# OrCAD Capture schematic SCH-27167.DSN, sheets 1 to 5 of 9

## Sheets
1 TWR-K60F120M MCU: size C; title: TWR-K60F120M; rev: B; company: Freescale Semiconductor; note: SCH-27167 PDF: SPF-27167; note: 6501 William Cannon Drive West; note: Austin, TX 78735-8598
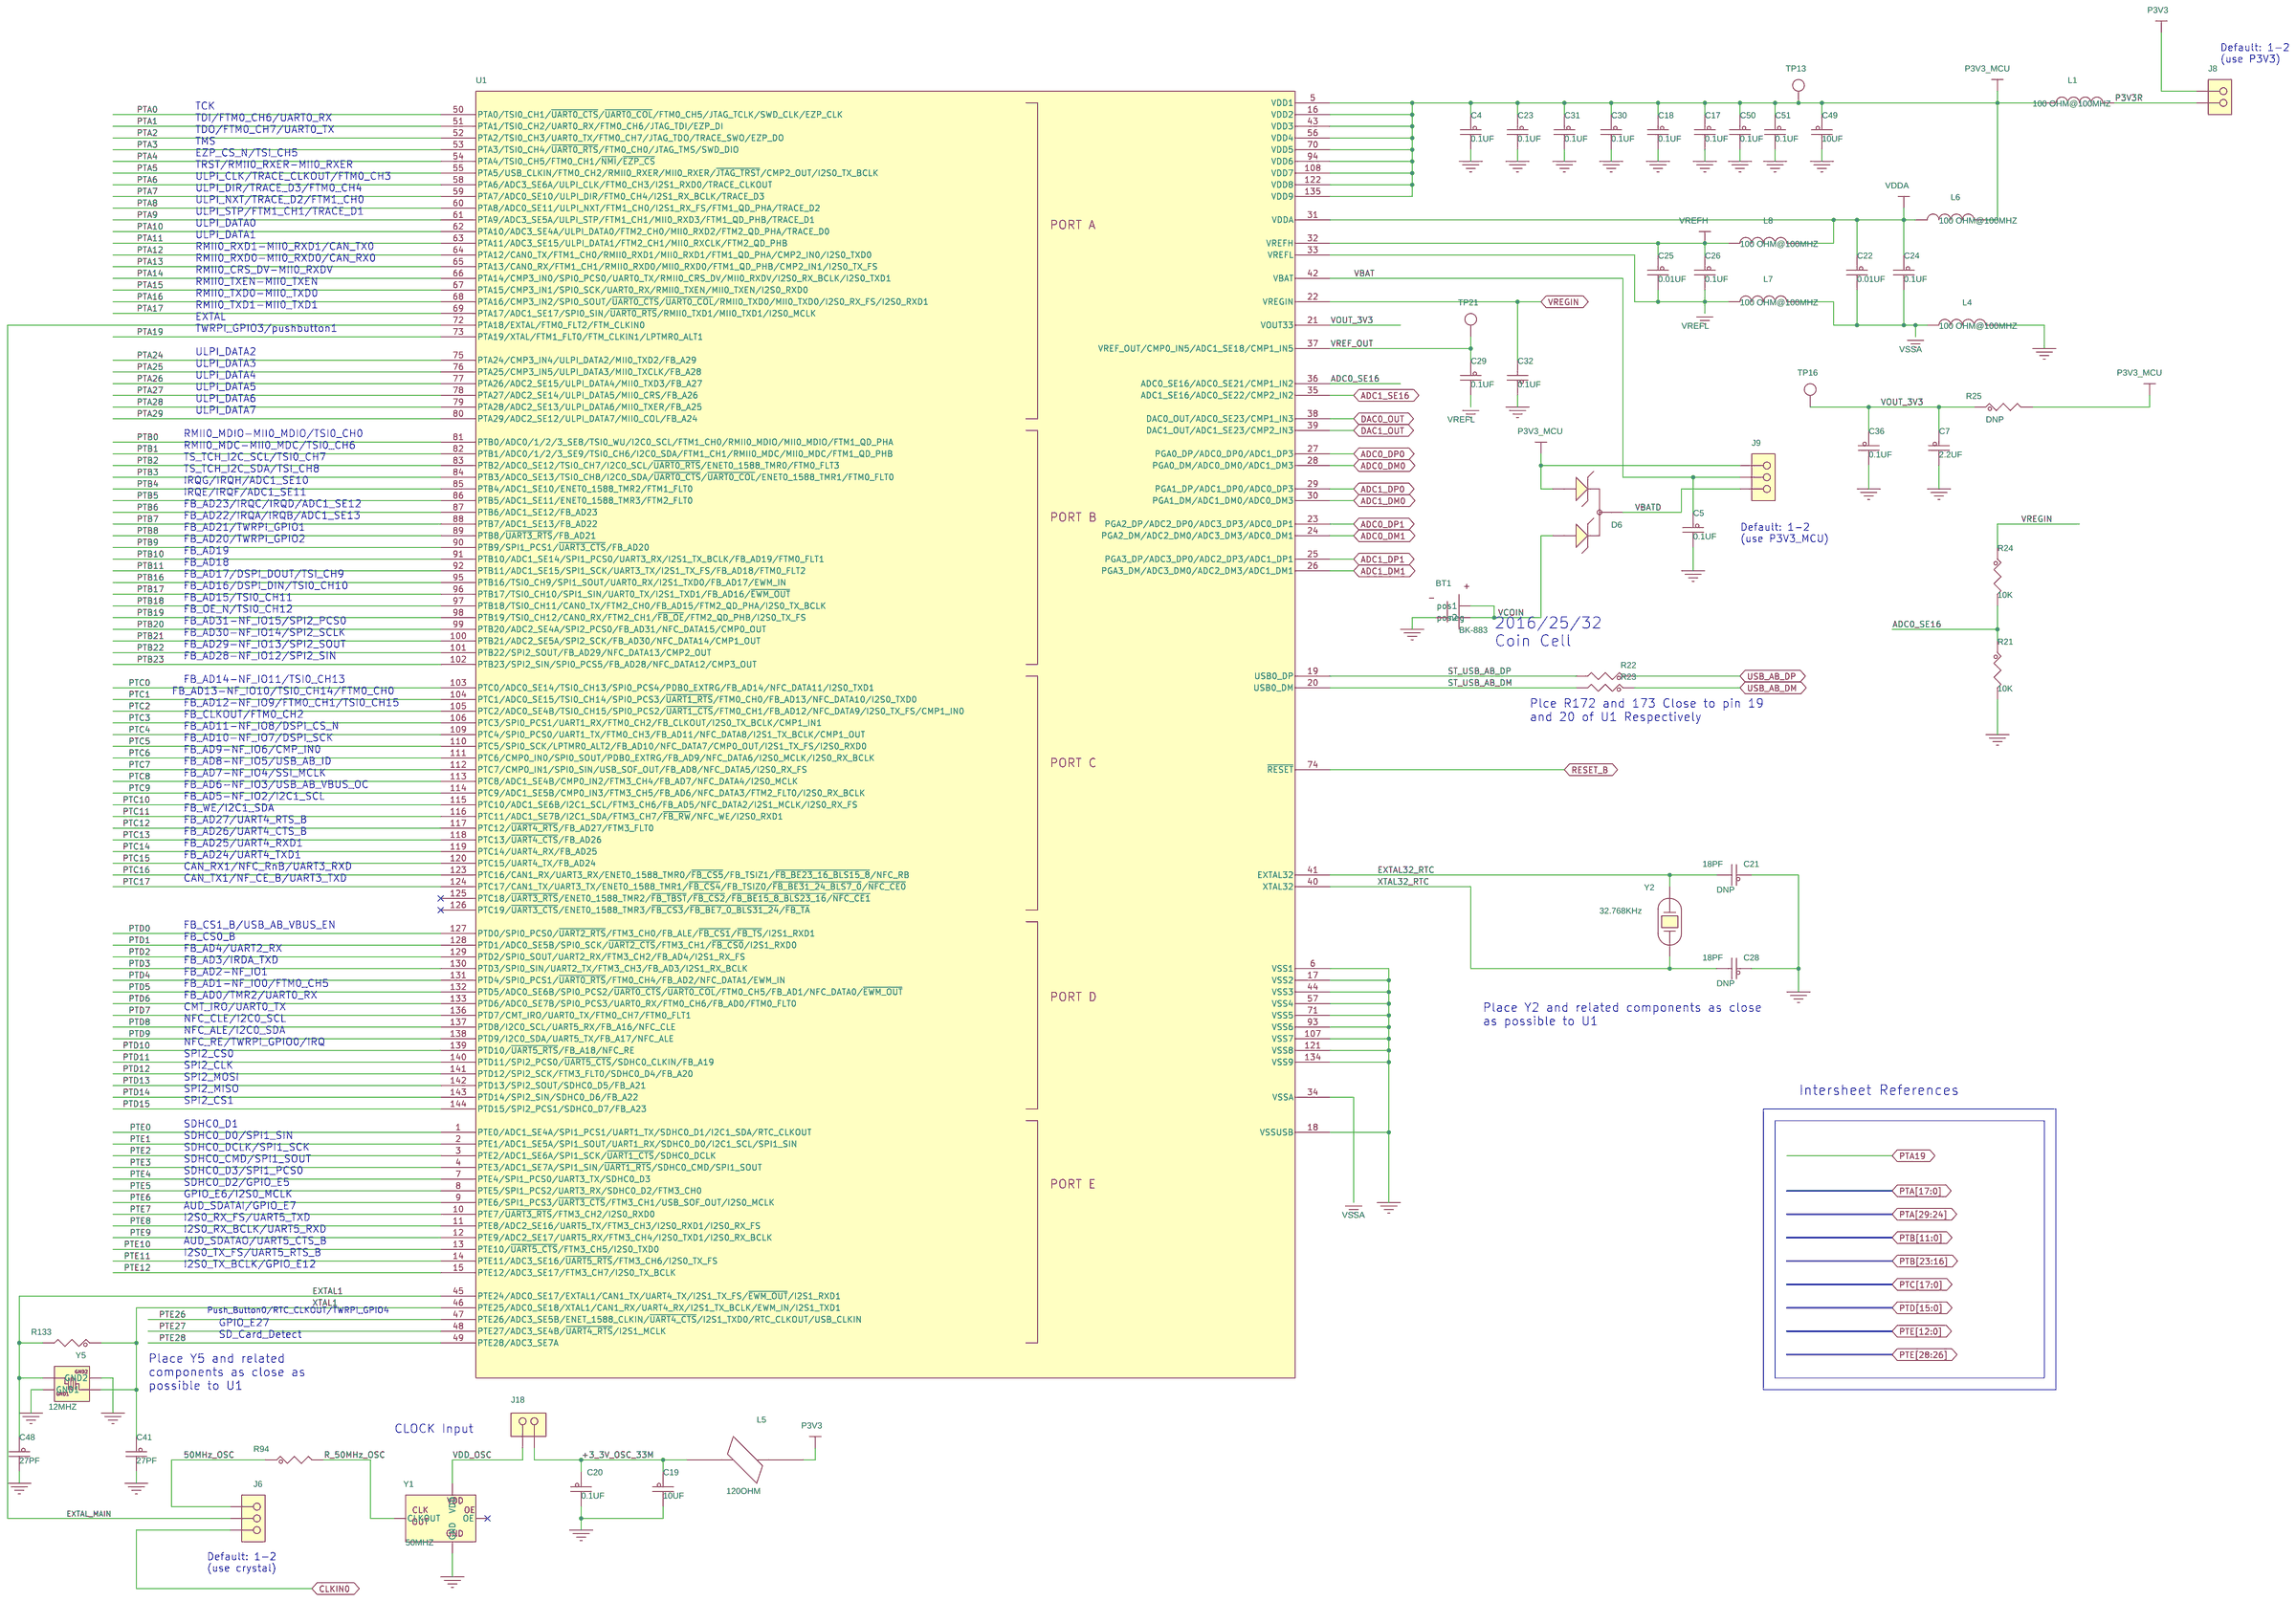
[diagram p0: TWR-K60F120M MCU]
2 USB/OSBDM/VTRAN/PWR: size C
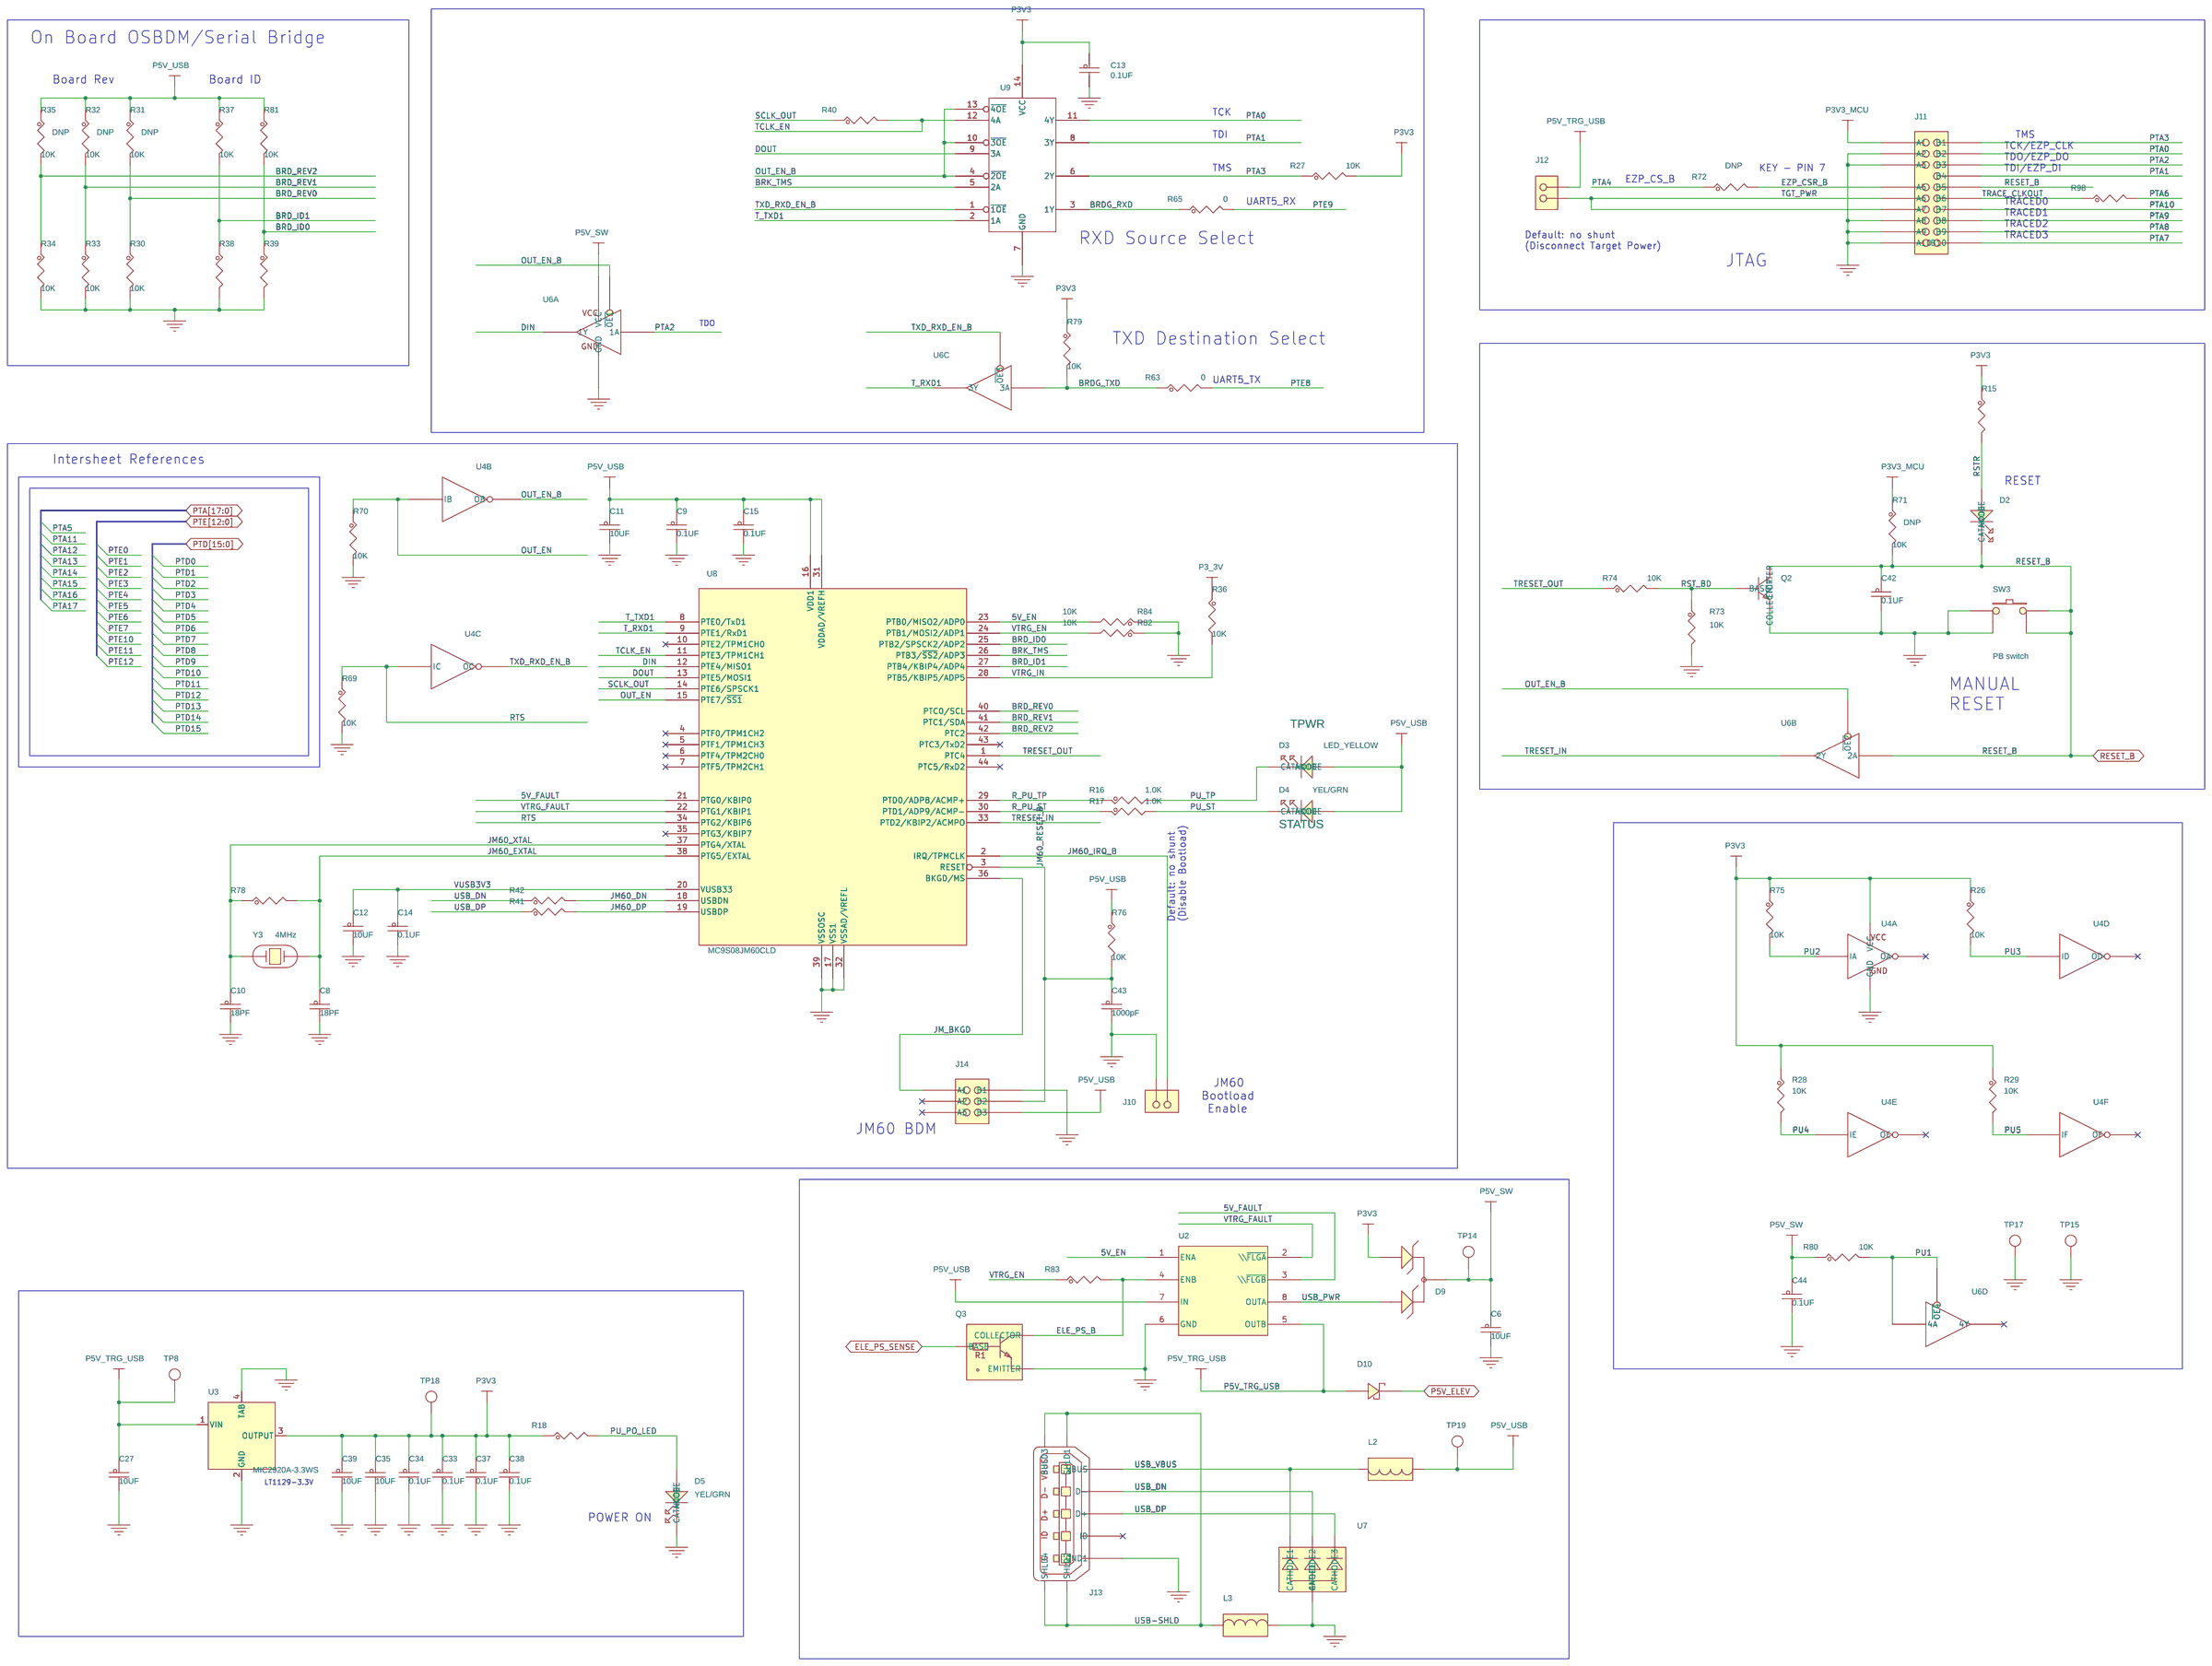
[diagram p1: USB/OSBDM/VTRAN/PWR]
3 Peripherals: size C
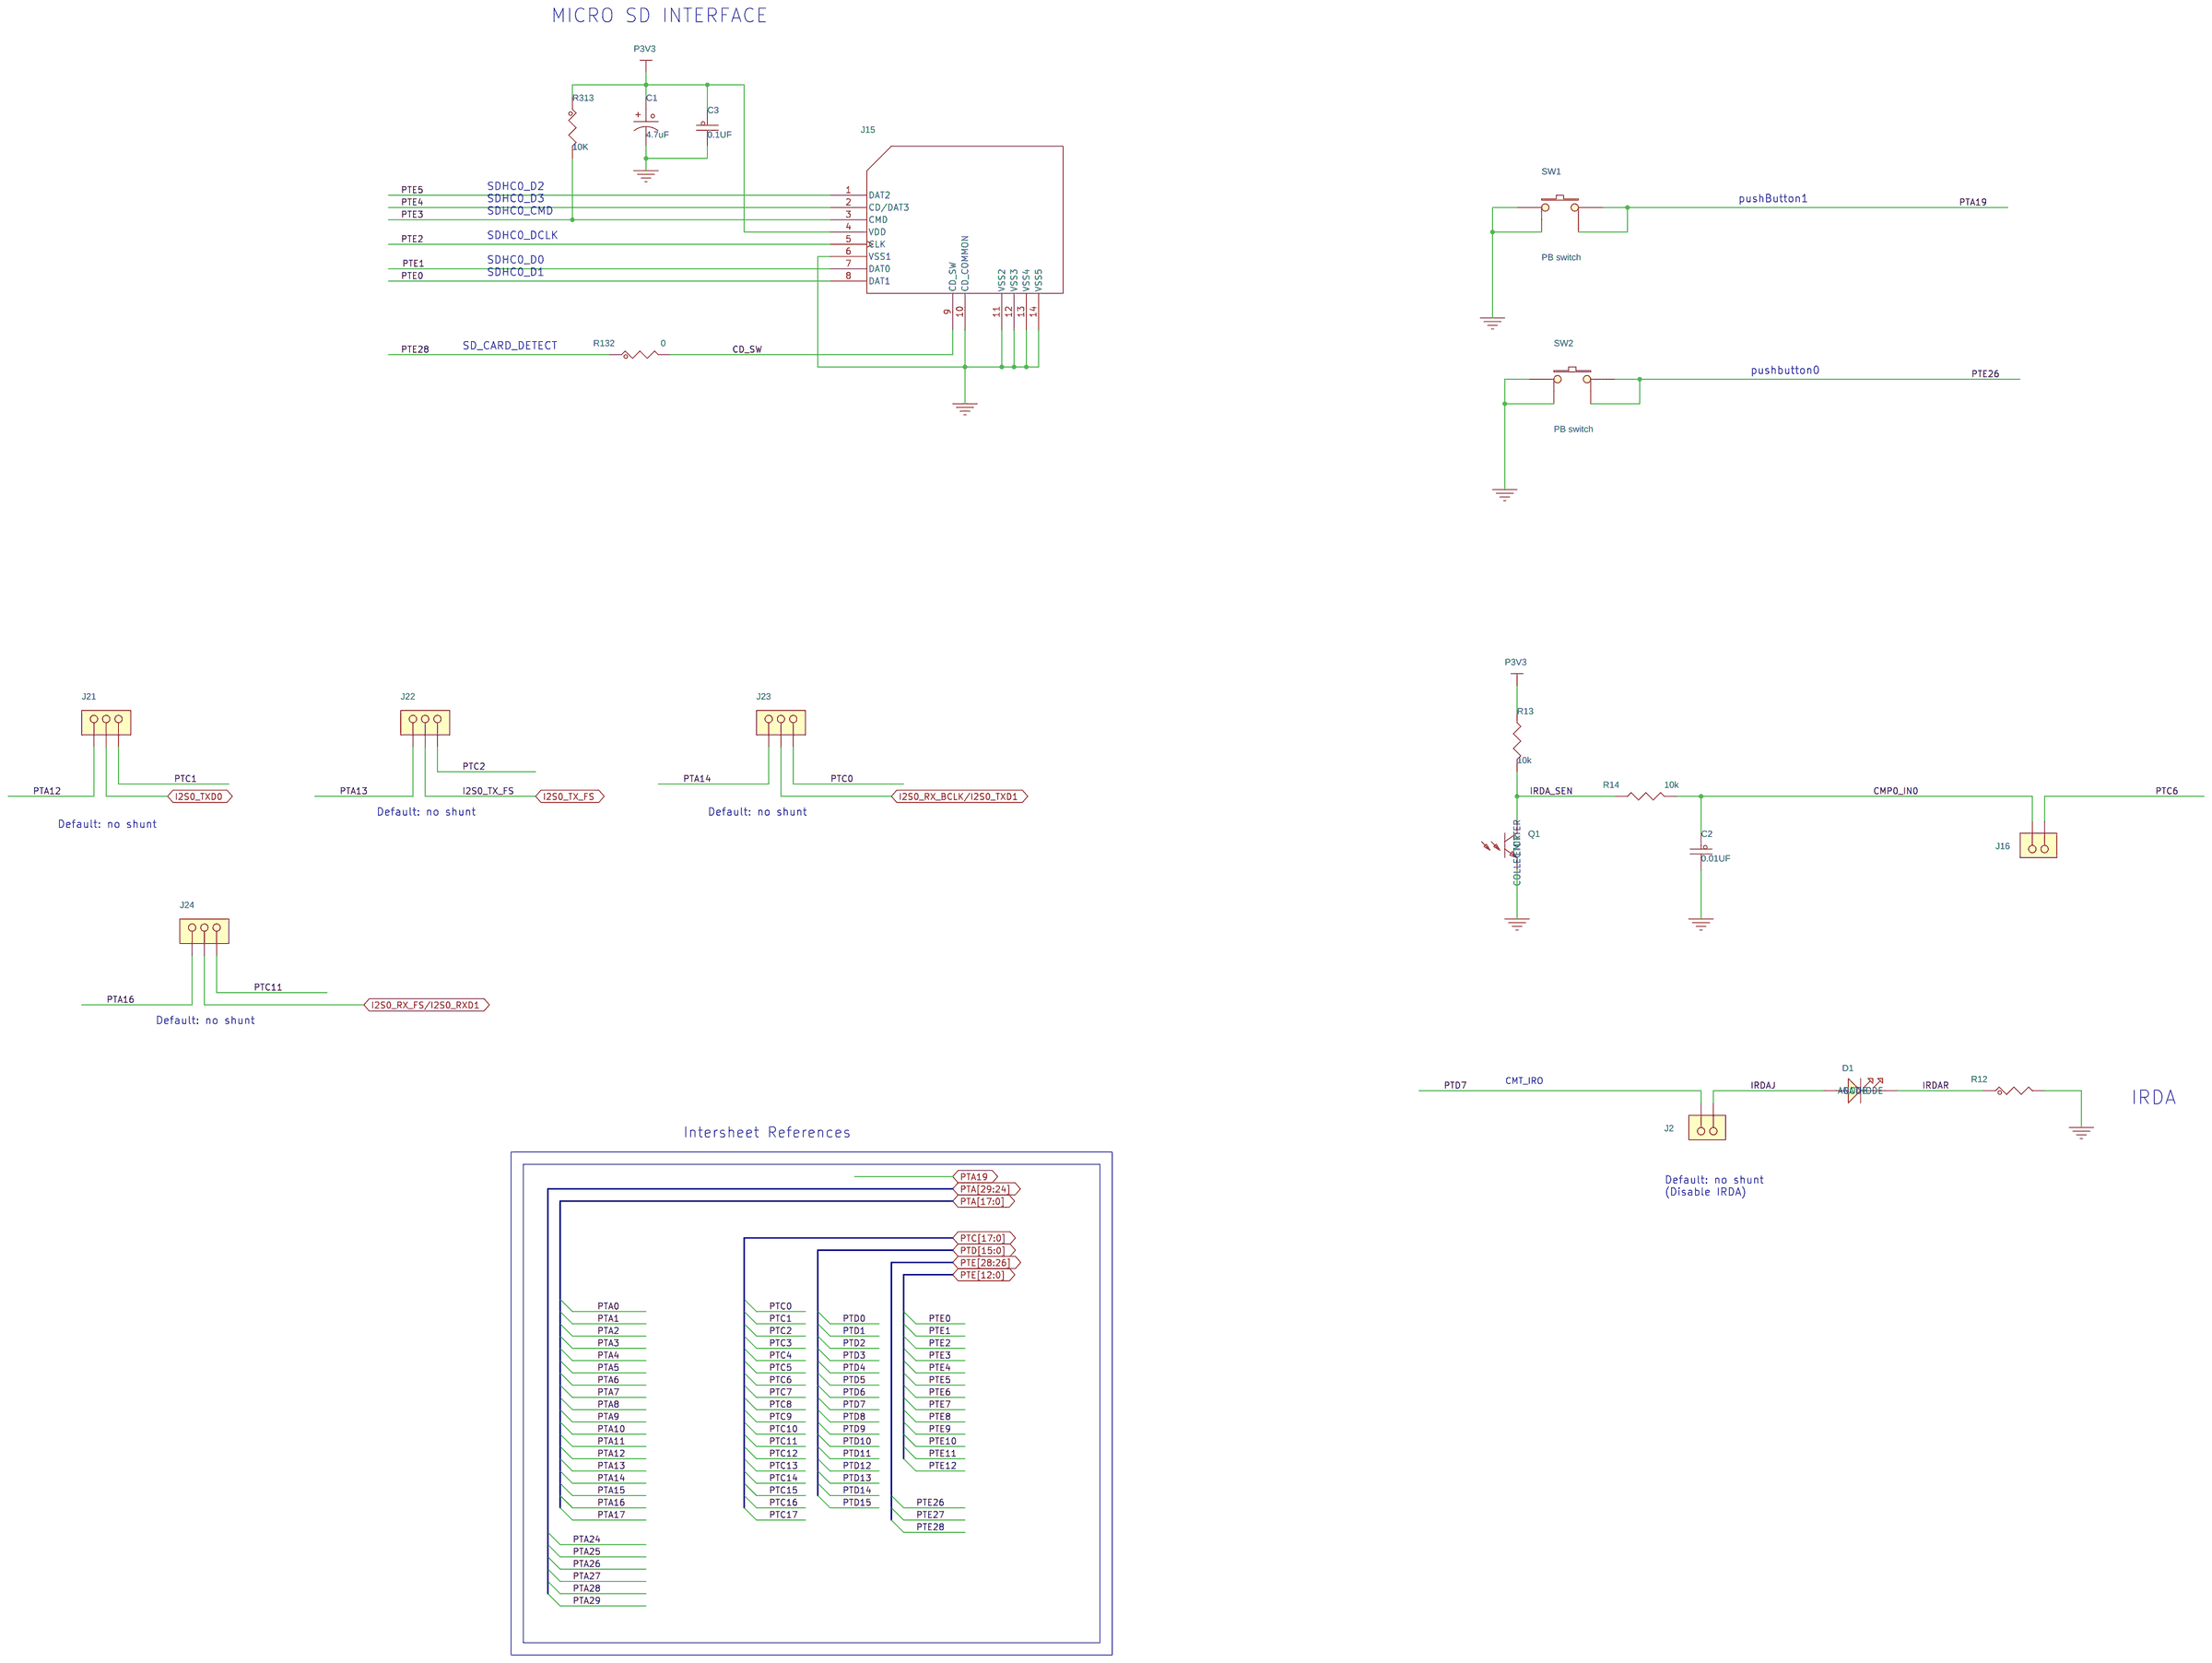
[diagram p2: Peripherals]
4 Sensors: size C
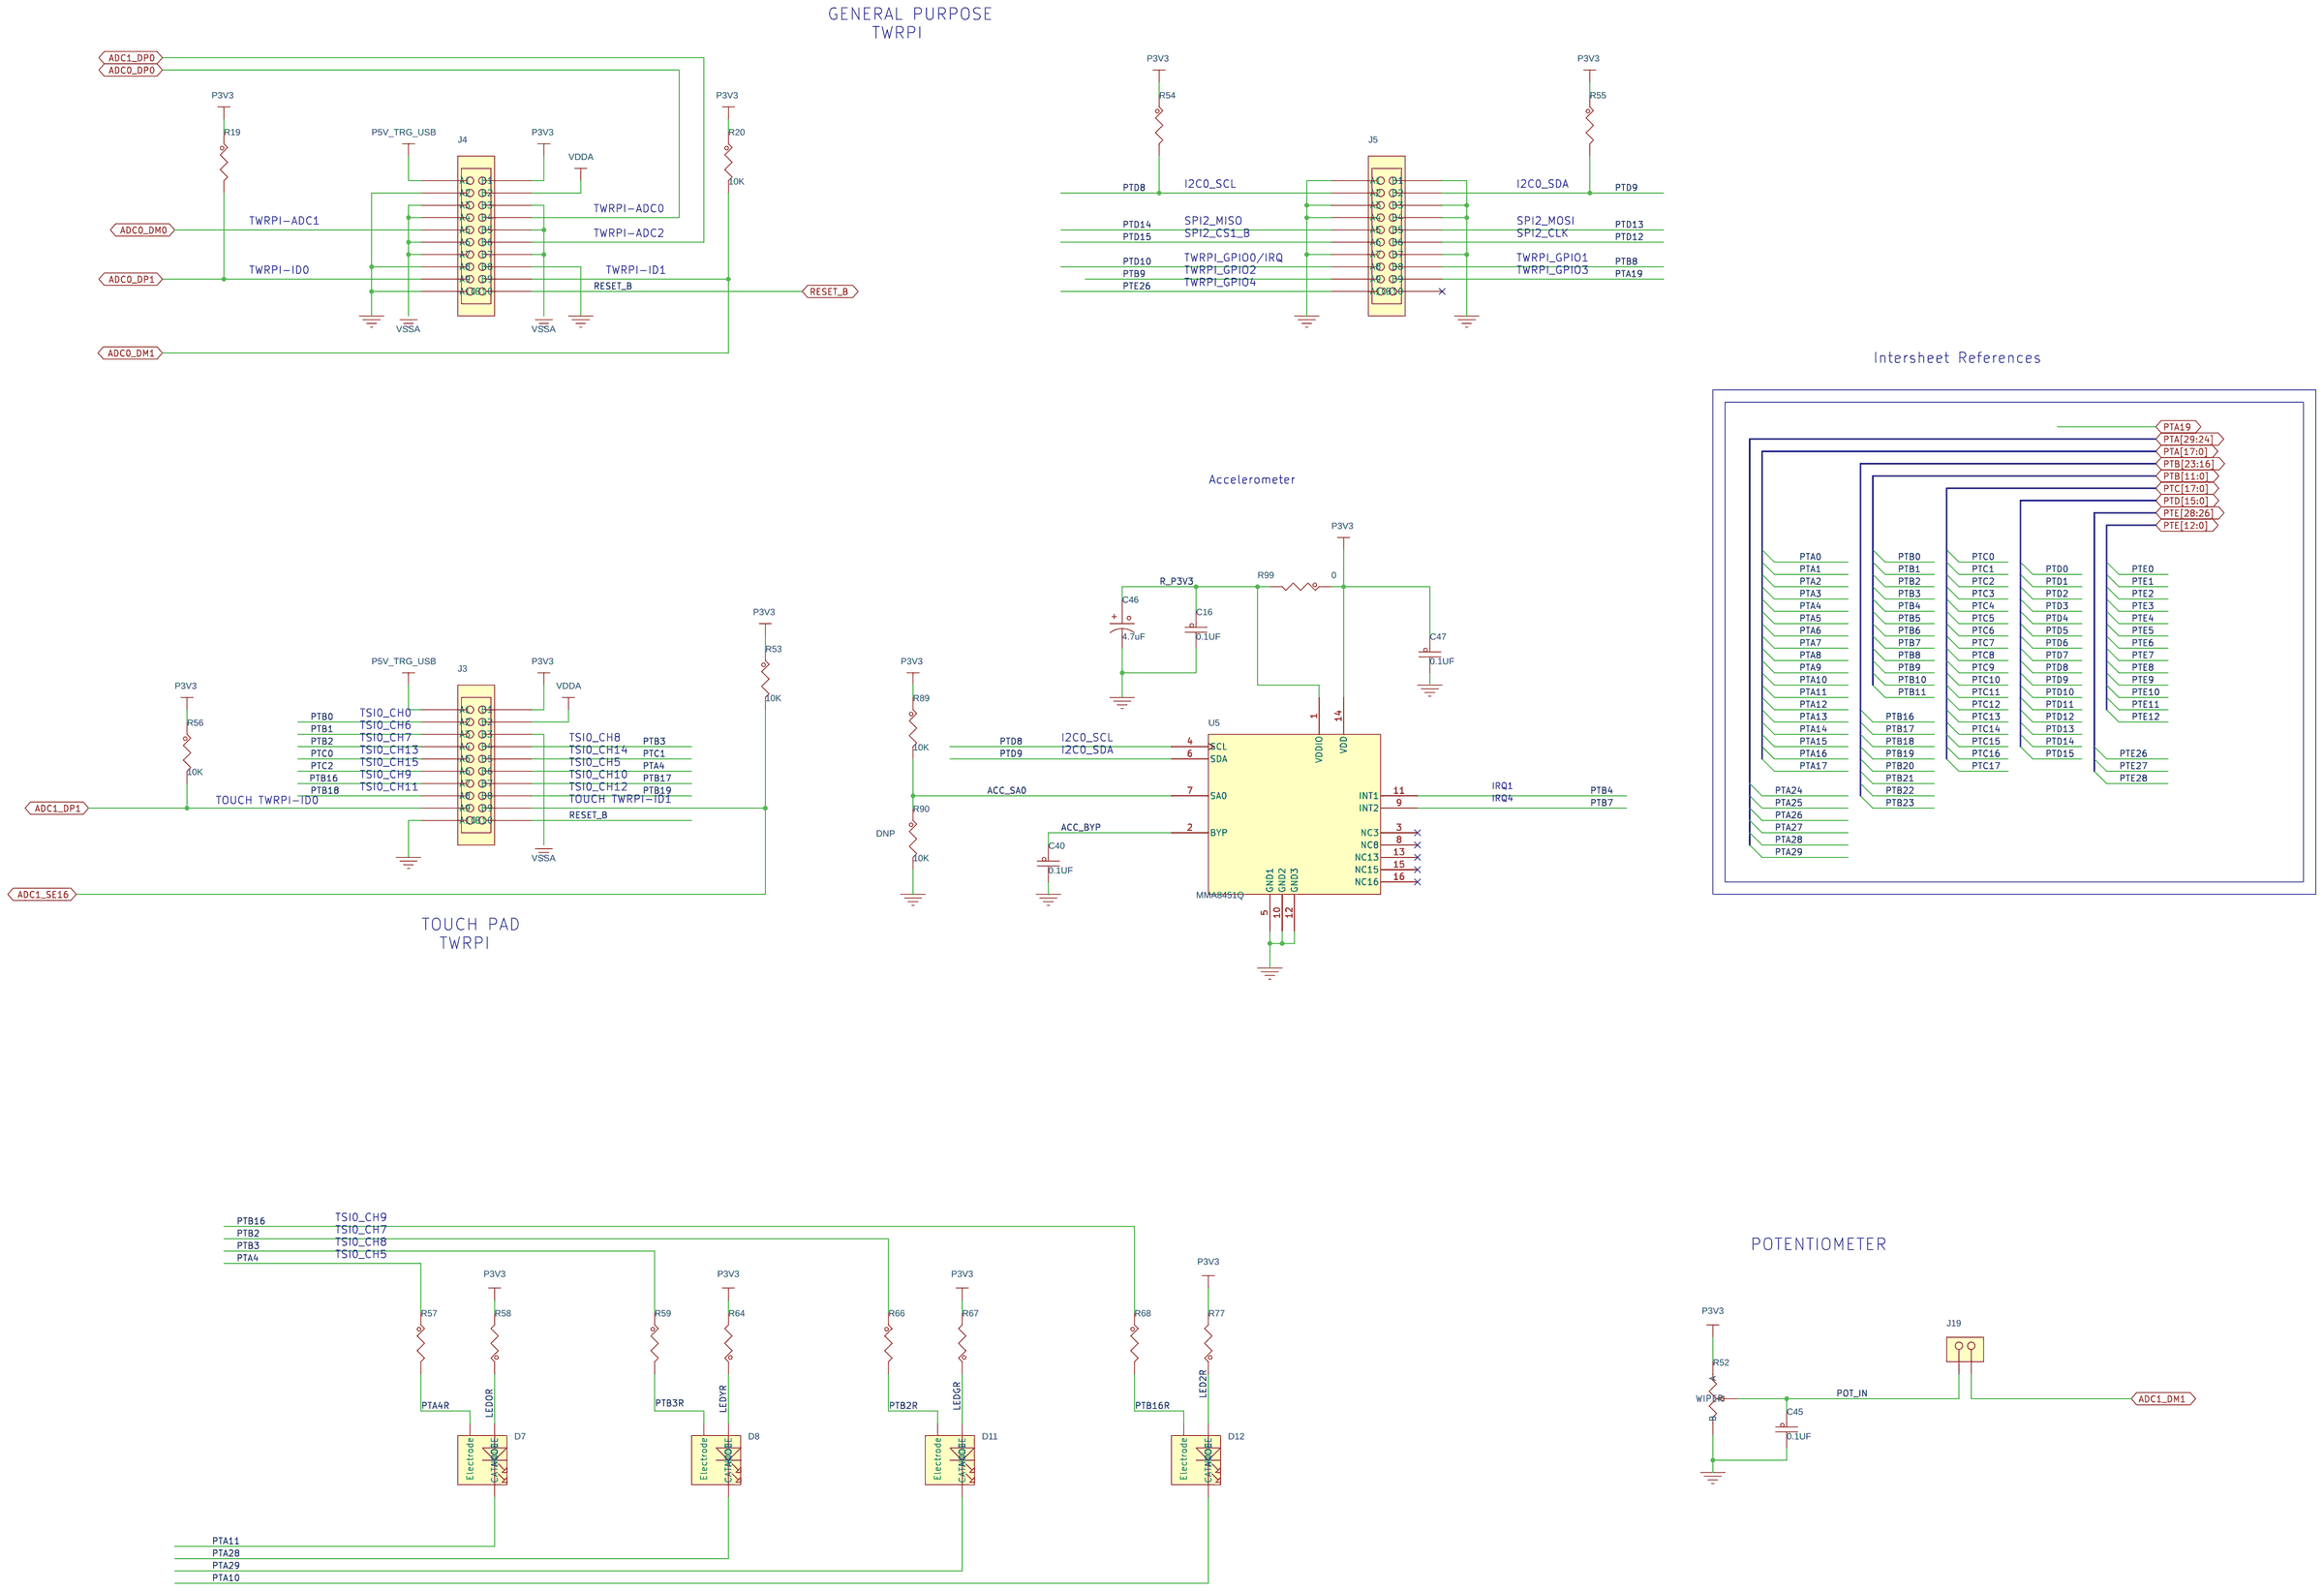
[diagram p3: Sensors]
5 NAND_Flash: size C
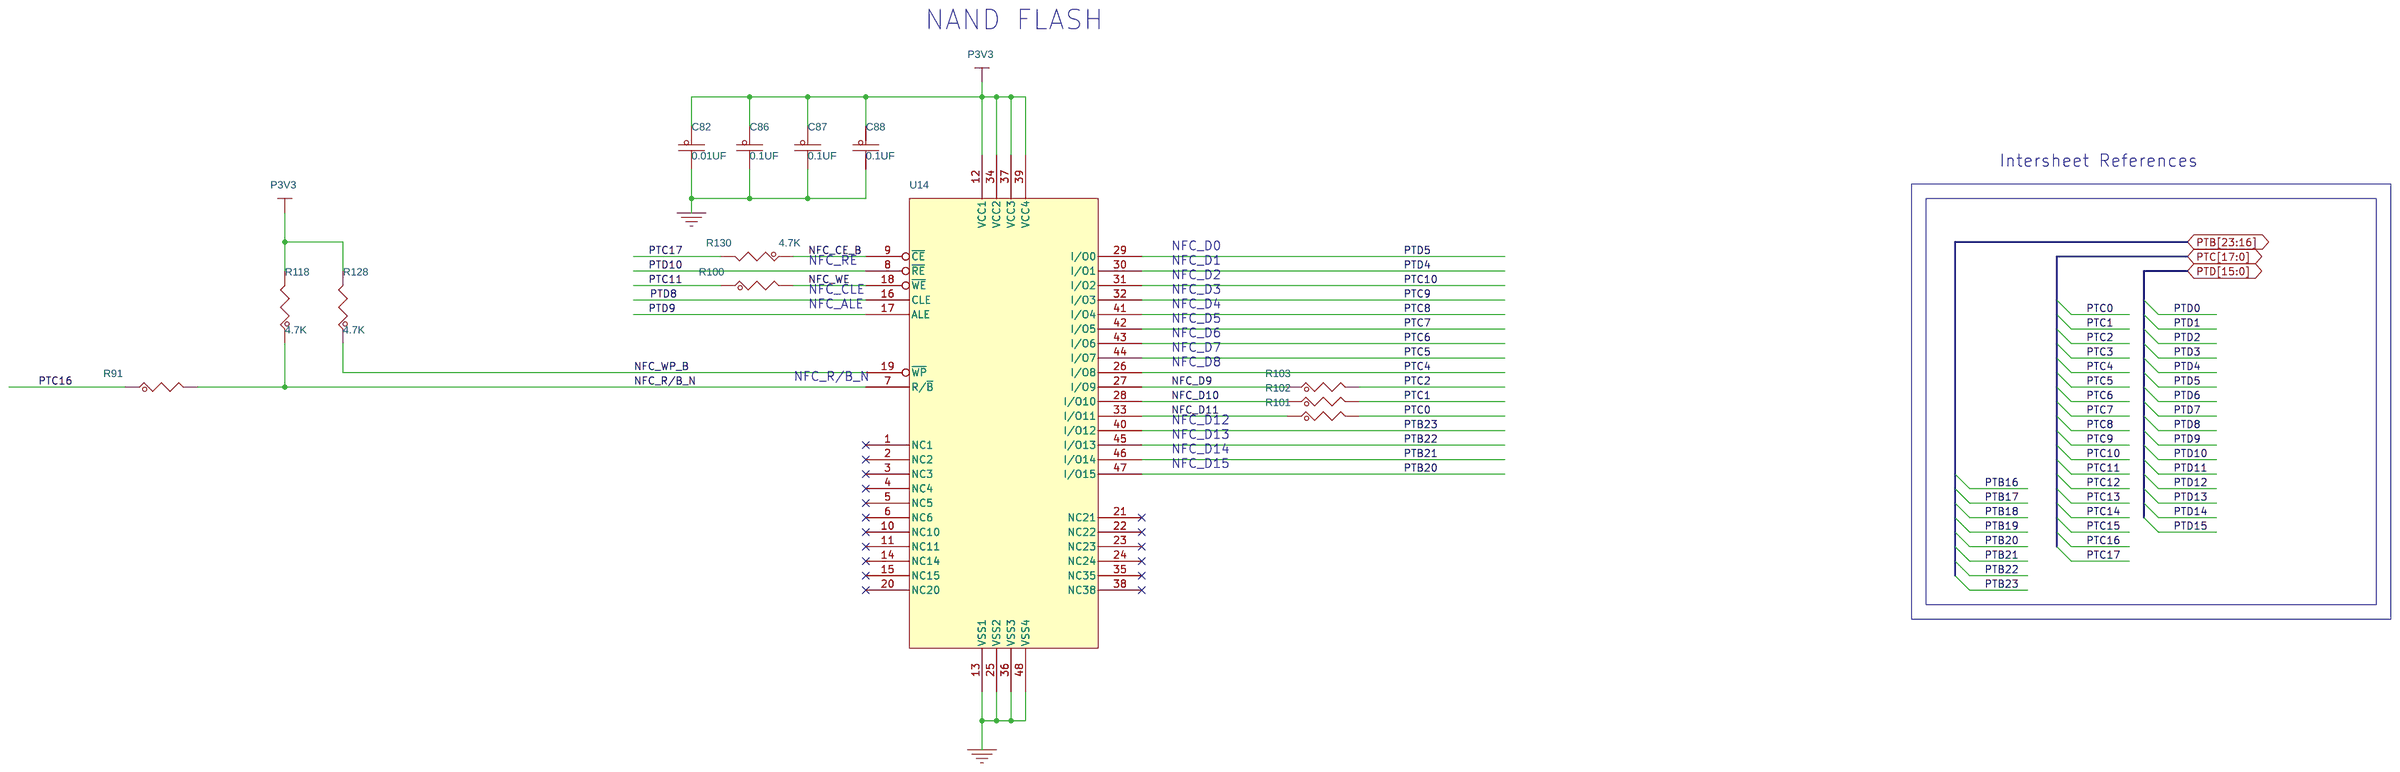
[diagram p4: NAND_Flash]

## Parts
sheet NAND_Flash
C82  0.01UF  [CC0402_25]
C86  0.1UF  [CC0603_OV]
C87  0.1UF  [CC0603_OV]
C88  0.1UF  [CC0603_OV]
R91  0  [RC0603_OV]
R100  0  [RC0603_OV]
R101  0  [RC0603_OV]
R102  0  [RC0603_OV]
R103  0  [RC0603_OV]
R118  4.7K  [RC0402_25]
R128  4.7K  [RC0402_25]
R130  4.7K  [RC0402_25]
U14  MT29F2G16ABAEAWP:E  [tsop48_18p5x12p4]
sheet Peripherals
C1  4.7uF  [cc3528-21]
C2  0.01UF  [CC0402_25]
C3  0.1UF  [CC0603_OV]
D1  QTLP610CIR  [diode_3p2x2p2]
J2  HDR 1X2 TH  [HDR102]
J15  Conn MicroSD  [CON_SDCARD_8F_SM_RA]
J16  HDR 1X2 TH  [HDR102]
J21  HDR TH 1X3  [HDR103]
J22  HDR TH 1X3  [HDR103]
J23  HDR TH 1X3  [HDR103]
J24  HDR TH 1X3  [HDR103]
Q1  QTLP610CPD  [QTLP610]
R12  33  [RC0603_OV]
R13  10k  [RC0402_25]
R14  10k  [RC0402_25]
R132  0  [RC0603_OV]
R313  10K  [RC0603_OV]
SW1  PB switch  [SW4_4MM]
SW2  PB switch  [SW4_4MM]
sheet Sensors
C16  0.1UF  [CC0603_OV]
C40  0.1UF  [CC0603_OV]
C45  0.1UF  [CC0603_OV]
C46  4.7uF  [cc3528-21]
C47  0.1UF  [CC0603_OV]
D7  LED_OR + ELECTRODE  [led2_electrode]
D8  LED_YEL + ELECTRODE  [LED2_ELECTRODE]
D11  LED_GRN + ELECTRODE  [LED2_ELECTRODE]
D12  LED2_ELECTRODE  [LED2_ELECTRODE]
J3  CON_2X10  [con_tfm_20m_50_sm]
J4  CON_2X10  [con_tfm_20m_50_sm]
J5  CON_2X10  [con_tfm_20m_50_sm]
J19  HDR 1X2 TH  [HDR102]
R19  10K  [RC0603_OV]
R20  10K  [RC0603_OV]
R52  5K  [pot3_3352t]
R53  10K  [RC0603_OV]
R54  4.70K  [RC0603_OV]
R55  4.70K  [RC0603_OV]
R56  10K  [RC0603_OV]
R57  0  [RC0603_OV]
R58  1.0K  [RC0402_25]
R59  0  [RC0603_OV]
R64  1.0K  [RC0402_25]
R66  0  [RC0603_OV]
R67  1.0K  [RC0402_25]
R68  0  [RC0603_OV]
R77  1.0K  [RC0402_25]
R89  10K  [RC0603_OV]
R90  10K  [RC0603_OV]
R99  0  [RC0603_OV]
U5  MMA8451Q  [QFN5X3_0P5_3X3]
sheet TWR-K60F120M MCU
BT1  BK-883  [skt_bat_780x1210]
C4  0.1UF  [CC0603_OV]
C5  0.1UF  [CC0603_OV]
C7  2.2UF  [CC0603_OV]
C17  0.1UF  [CC0603_OV]
C18  0.1UF  [CC0603_OV]
C19  10UF  [CC0805_OV]
C20  0.1UF  [CC0603_OV]
C21  18PF  [CC0603_OV]
C22  0.01UF  [CC0402_25]
C23  0.1UF  [CC0603_OV]
C24  0.1UF  [CC0603_OV]
C25  0.01UF  [CC0402_25]
C26  0.1UF  [CC0603_OV]
C28  18PF  [CC0603_OV]
C29  0.1UF  [CC0603_OV]
C30  0.1UF  [CC0603_OV]
C31  0.1UF  [CC0603_OV]
C32  0.1UF  [CC0603_OV]
C36  0.1UF  [CC0603_OV]
C41  27PF  [CC0402_25]
C48  27PF  [CC0402_25]
C49  10UF  [CC0805_OV]
C50  0.1UF  [CC0603_OV]
C51  0.1UF  [CC0603_OV]
D6  BAT54C  [sot-23]
J6  HDR TH 1X3  [HDR103]
J8  HDR 1X2 TH  [HDR102]
J9  HDR TH 1X3  [HDR103]
J18  HDR 1X2 TH  [HDR102]
L1  100 OHM@100MHZ  [IND_0603]
L4  100 OHM@100MHZ  [IND_0603]
L5  120OHM  [IND_0603]
L6  100 OHM@100MHZ  [IND_0603]
L7  100 OHM@100MHZ  [IND_0603]
L8  100 OHM@100MHZ  [IND_0603]
R21  10K  [RC0603_OV]
R22  33  [RC0603_OV]
R23  33  [RC0603_OV]
R24  10K  [RC0603_OV]
R25  0  [RC0805_OV]
R94  68  [RC0402_25]
R133  10M  [RC0402_25]
TP13  TPAD_040  [TPAD_040]
TP16  TPAD_040  [TPAD_040]
TP21  TPAD_040  [TPAD_040]
U1  PK60FN1M0VLQ12  [LQFP144_0P5_20X20MM]
Y1  50MHZ  [XTLOSC4_SM]
Y2  32.768KHz  [XTL2_ECS_SM]
Y5  12MHZ  [xtal4_3p3x2p6_sm_fl]
sheet USB/OSBDM/VTRAN/PWR
C6  10UF  [CC0805_OV]
C8  18PF  [CC0603_OV]
C9  0.1UF  [CC0603_OV]
C10  18PF  [CC0603_OV]
C11  10UF  [CC0805_OV]
C12  10UF  [CC0805_OV]
C13  0.1UF  [CC0603_OV]
C14  0.1UF  [CC0603_OV]
C15  0.1UF  [CC0603_OV]
C27  10UF  [CC0805_OV]
C33  0.1UF  [CC0603_OV]
C34  0.1UF  [CC0603_OV]
C35  10UF  [CC0805_OV]
C37  0.1UF  [CC0603_OV]
C38  0.1UF  [CC0603_OV]
C39  10UF  [CC0805_OV]
C42  0.1UF  [CC0603_OV]
C43  1000pF  [CC0805_OV]
C44  0.1UF  [CC0603_OV]
D2  ORANGE  [LED_0603]
D3  LED_YELLOW  [LED_0603]
D4  YEL/GRN  [LED_0603]
D5  YEL/GRN  [LED_0603]
D9  BAT54C  [sot-23]
D10  MSS1P3L  [smb_2p7x1p4]
J10  HDR 1X2 TH  [HDR102]
J11  HDR_19P  [con_ftsh_19m_50_sm]
J12  HDR 1X2 TH  [HDR102]
J13  CONN USB MINI-B 1x5  [con5_usb_mini_a_smt]
J14  HDR_2X3  [HDR203_TSM_SM]
L2  330 OHM  [IND_0805]
L3  330 OHM  [IND_0805]
Q2  MMBT3904LT1G  [SOT23]
Q3  PDTC115T  [sot416]
R15  330  [RC0402_25]
R16  1.0K  [RC0402_25]
R17  1.0K  [RC0402_25]
R18  270  [RC0402_25]
R26  10K  [RC0603_OV]
R27  10K  [RC0603_OV]
R28  10K  [RC0603_OV]
R29  10K  [RC0603_OV]
R30  10K  [RC0603_OV]
R31  10K  [RC0603_OV]
R32  10K  [RC0603_OV]
R33  10K  [RC0603_OV]
R34  10K  [RC0603_OV]
R35  10K  [RC0603_OV]
R36  10K  [RC0603_OV]
R37  10K  [RC0603_OV]
R38  1.3K  [RC0402_25]
R39  1.3K  [RC0402_25]
R40  4.99K  [RC0402_25]
R41  33  [RC0603_OV]
R42  33  [RC0603_OV]
R63  0  [RC0603_OV]
R65  0  [RC0603_OV]
R69  10K  [RC0603_OV]
R70  10K  [RC0603_OV]
R71  10K  [RC0603_OV]
R72  0  [RC0603_OV]
R73  10K  [RC0603_OV]
R74  10K  [RC0603_OV]
R75  10K  [RC0603_OV]
R76  10K  [RC0603_OV]
R78  10M  [RC0402_25]
R79  10K  [RC0603_OV]
R80  10K  [RC0603_OV]
R81  10K  [RC0603_OV]
R82  10K  [RC0603_OV]
R83  2.2K  [RC0402_25]
R84  10K  [RC0603_OV]
R98  0  [RC0603_OV]
SW3  PB switch  [SW4_4MM]
TP8  TPAD_040  [TPAD_040]
TP14  TPAD_040  [TPAD_040]
TP15  TEST POINT BLACK  [TEST_LOOP]
TP17  TEST POINT BLACK  [TEST_LOOP]
TP18  TPAD_040  [TPAD_040]
TP19  TPAD_040  [TPAD_040]
U2  MIC2026-1YM  [SO8]
U3  MIC2920A-3.3WS  [sot223]
U4  SN74LVC04APWE4  [TSSOP-14]  (sections A,B,C,D,E,F)
U6  74HCT125  [soic14]  (sections A,B,C,D)
U7  SP0503B  [sot_143]
U8  MC9S08JM60CLD  [tqfp44]
U9  74LVC125  [TSSOP14]
Y3  4MHz  [xtl2_ecs_csm7_sm]

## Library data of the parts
C2 C22 C25 C82 = CAP_NP: CAP CER 0.01UF 50V 10% X7R 0402; AGILE_PN: 150-30114; CAD_APPROVED: Yes; FPLIST: CC0402_25,CC0402_HD,0402_CC; HEIGHT: 0.74 MM; MFG_NAME01: MURATA; MFG_PN01: GCM155R71H103KA55D; ROHS: Yes; Tolerance: 10%
C3-C5 C9 C13-C18 C23 C24 C26 C29-C34 C36-C38 C40 C42 C44 C45 C47 C50 C51 C86-C88 = CAP_NP: CAP CER 0.10UF 25V 10% X7R 0603; AGILE_PN: 150-75016; CAD_APPROVED: Yes; FPLIST: CC0603_OV,CC0603,0603_CC; HEIGHT: 0.97 MM; MFG_NAME01: KEMET; MFG_PN01: C0603C104K3RAC; ROHS: Yes; Tolerance: 10%
R57 R59 R63 R65 R66 R68 R91 R98 R100-R103 R132 = RES: RES MF ZERO OHM 1/10W -- 0603; AGILE_PN: 470-75407; CAD_APPROVED: Yes; FPLIST: RC0603_OV,RC0603,R603-X2,0603_CC; MFG_NAME01: VISHAY INTERTECHNOLOGY; MFG_PN01: CRCW06030000Z0EA; ROHS: Yes; Tolerance: 1%
R118 R128 R130 = RES: RES MF 4.7K 1/16W 5% 0402; AGILE_PN: 470-75626; CAD_APPROVED: Yes; FPLIST: RC0402_25,RC0402_HD,0402_CC; HEIGHT: 0.41mm; MFG_NAME01: YAGEO AMERICA; MFG_PN01: RC0402JR-074K7L; ROHS: Yes; SIGNAL_MODEL: DEFAULT_RESISTOR_4700OHM_2_1; TOL: 5%; Tolerance: 5%
U14 = MT29F2G16AADWP: IC MEM NAND FLASH 128MX16 2.7-3.6V TSOP48; AGILE_PN: 342-00497; CAD_APPROVED: Yes; HEIGHT: 1.2MM; MFG_NAME01: MICRON; ROHS: Yes
C1 C46 = CAP_POL: CAP TANT 4.7UF 25V 10% -- 3528-21; AGILE_PN: 150-78522; CAD_APPROVED: Yes; HEIGHT: 2.1MM; MFG_NAME01: AVX; MFG_PN01: TAJB475K025RNJ; ROHS: Yes; Tolerance: 10%
D1 = LED: DIODE EMITTING 65MA 940NM SMT; AGILE_PN: 480-77974; CAD_APPROVED: Yes; HEIGHT: 1.1MM; MFG_NAME01: FAIRCHILD; ROHS: Yes
J2 J8 J10 J12 J16 J18 J19 = CONN_HDR_2X1: HDR 1X2 TH 100MIL SP 339H AU 98L; AGILE_PN: 210-75439; CAD_APPROVED: YES; HEIGHT: 8.71 MM; MFG_NAME01: SAMTEC; MFG_PN01: TSW-102-07-G-S; ROHS: Yes
J15 = CONN_MICRO_SD_CARD_REVERSED: CON MICRO_SD 1.1MM 1.8MM -- Reverse Mount; AGILE_PN: 211-78813; CAD_APPROVED: Yes; HEIGHT: 1.95 MM; MFG_NAME01: Molex; MFG_PN01: 5027740891; ROHS: Yes
J6 J9 J21-J24 = CONN_HDR_3X1: HDR 1X3 TH 100MIL SP 339H AU 100L; AGILE_PN: 210-75726; CAD_APPROVED: Yes; HEIGHT: 8.65MM; MFG_NAME01: SAMTEC; MFG_PN01: TSW-103-07-G-S; ROHS: Yes
Q1 = TRAN_PHOTO: TRAN PHOTO 30V 860NM SMT; AGILE_PN: 480-77973; CAD_APPROVED: Yes; HEIGHT: 1.1MM; MFG_NAME01: FAIRCHILD; ROHS: Yes
R12 R22 R23 R41 R42 = RES: RES MF 33 OHM 1/10W 1% 0603; AGILE_PN: 470-75389; CAD_APPROVED: Yes; FPLIST: RC0603_OV,RC0603,0603_CC; MFG_NAME01: KOA SPEER; MFG_PN01: RK73H1JTTD33R0F; ROHS: Yes; Tolerance: 1%
R13 R14 = Res: RES MF 10K 1/16W 1% 0402; AGILE_PN: 470-80310; CAD_APPROVED: Yes; FPLIST: RC0402_25,RC0402_HD,0402_CC; MFG_NAME01: KOA SPEER; MFG_PN01: RK73H1ETTPL1002F; Mfg: KOA; Mfg Part No: RK73B1ETTP103J; ROHS: Yes; ROOM: DDR; Sub_Type: Chip; Tolerance: 1%
R20 R21 R24 R26-R30 R33 R34 R36 R37 R53 R56 R69 R70 R73-R76 R79-R82 R84 R89 R313 = RES: RES MF 10K 1/10W 5% 0603; AGILE_PN: 470-75410; CAD_APPROVED: Yes; FPLIST: RC0402_25,RC0402_HD,0402_CC; MFG_NAME01: KOA SPEER; MFG_PN01: RK73B1JTTD103J; ROHS: Yes; Tolerance: 5%
SW1-SW3 = SW_TACT-SPST-2_SM: SW SMT 4.0MM FMS 0.1A MAX 16V MAX ROHS COMPLIANT; AGILE_PN: 510-75078; CAD_APPROVED: Yes; HEIGHT: 4.19 MM; MFG_NAME01: BOURNS; MFG_PN01: 7914J-1-000E; ROHS: Yes
D7 = LED2_ELECTRODE: SUBASSEMBLY LED OR SGL 20MA 1206 + RECTANGULAR ELECTRODE 590X270MIL; AGILE_PN: 750-77162; CAD_APPROVED: Yes; FPLIST: led2_electrode,led2_electrode_A; HEIGHT: 1.1MM; MFG_NAME01: subassembly; MFG_PN01: 510-77640, 370-76518; ROHS: Yes
D8 = LED2_ELECTRODE: SUBASSEMBLY LED YEL SGL 20MA 1206 + RECTANGULAR ELECTRODE 590X270MIL; AGILE_PN: 750-77164; CAD_APPROVED: Yes; HEIGHT: 1.1MM; MFG_NAME01: SUBASSEMBLY; MFG_PN01: 510-77640, 370-76520; ROHS: Yes
D11 = LED2_ELECTRODE: SUBASSEMBLY LED GRN SGL 20MA 1206 + RECTANGULAR ELECTRODE 590X270MIL; AGILE_PN: 750-77163; CAD_APPROVED: Yes; HEIGHT: 1.1MM; MFG_NAME01: SUBASSEMBLY; MFG_PN01: 510-77640, 370-76519; ROHS: Yes
D12 = LED2_ELECTRODE: SUBASSY LED BL SGL 20MA 1206 + RECTANGULAR ELECTRODE 590X270MIL; AGILE_PN: 750-77055; CAD_APPROVED: Yes; HEIGHT: 1.1MM; MFG_NAME01: SUBASSEMBLY; MFG_PN01: 370-76430,510-77640; ROHS: Yes
J3 = CONN_SHRHDR_10X2: CON 2X10 PLUG SHRD SMT 50MIL CTR 440H AU; AGILE_PN: 211-78842; CAD_APPROVED: Yes; HEIGHT: 11.18MM; MFG_NAME01: SAMTEC; MFG_PN01: TFC-110-32-L-D-A-K; ROHS: Yes
J4 J5 = CONN_SHRHDR_10X2: CON 2X10 PLUG SHRD SMT 50MIL CTR 237H AU; AGILE_PN: 211-78839; CAD_APPROVED: Yes; HEIGHT: 6.02 MM; MFG_NAME01: SAMTEC; MFG_PN01: TFC-110-02-L-D-A-K; ROHS: Yes
R19 = RES: RES MF 10K 1/10W 5% 0603; AGILE_PN: 470-75410; CAD_APPROVED: Yes; FPLIST: RC0603_OV,RC0603,0603_CC; MFG_NAME01: KOA SPEER; MFG_PN01: RK73B1JTTD103J; ROHS: Yes; Tolerance: 5%
R52 = POT: RES POT 5K 1/2W 20% TH; AGILE_PN: 470-80115; CAD_APPROVED: Yes; MFG_NAME01: BOURNS; MFG_PN01: 3352T-1-502LF; ROHS: Yes; Tolerance: 20%
R54 R55 = RES: RES MF 4.70K 1/10W 1% 0603; AGILE_PN: 470-75430; CAD_APPROVED: Yes; FPLIST: RC0603_OV,RC0603,0603_CC; MFG_NAME01: KOA SPEER; MFG_PN01: RK73H1JTTD4701F; ROHS: Yes; Tolerance: 1%
R16 R17 R58 R64 R67 R77 = RES: RES MF 1.0K 1/16W 1% 0402; AGILE_PN: 470-76037; CAD_APPROVED: Yes; FPLIST: RC0402_25,RC0402_HD,RC0402_X2,0402_CC; MFG_NAME01: KOA SPEER; MFG_PN01: RK73H1ETTP1001F; ROHS: Yes; Tolerance: 1%
R31 R32 R35 R71 R90 = RES: RES MF 10K 1/10W 5% 0603; AGILE_PN: 470-75410; ASSY_OPT: DNP; CAD_APPROVED: Yes; FPLIST: RC0402_25,RC0402_HD,0402_CC; MFG_NAME01: KOA SPEER; MFG_PN01: RK73B1JTTD103J; ROHS: Yes; Tolerance: 5%
R99 = RES: RES MF ZERO OHM 1/10W 1% 0603; AGILE_PN: 470-80217; CAD_APPROVED: Yes; FPLIST: RC0603_OV,RC0603,R603-X2,0603_CC; MFG_NAME01: MULTICOMP; MFG_PN01: MC0603SAF0000T5E; ROHS: Yes; Tolerance: 1%
U5 = MMA8451Q_16P_A: IC 3-AXIS DIG ACCELEROMETER 14/8BIT 1.95-3.6V QFN16; AGILE_PN: 315-79075; CAD_APPROVED: Yes; HEIGHT: 1MM; MFG_NAME01: FREESCALE SEMICONDUCTOR; MFG_PN01: MMA8451QT; ROHS: Yes
BT1 = BATTERY_SKT_3V: HOLDER COIN CELL 2032 SMT; AGILE_PN: 801-75674; CAD_APPROVED: Yes; HEIGHT: 3.96MM; MFG_NAME01: MEMORY PROTECTION DEVICES INC; MFG_PN01: BK-883-TR; ROHS: Yes
C7 = CAP_NP: CAP CER 2.2UF 10V 10% X7R 0603; AGILE_PN: 150-78564; CAD_APPROVED: Yes; FPLIST: CC0603_OV,CC0603,0603_CC; HEIGHT: 1.25MM; MFG_NAME01: MURATA; MFG_PN01: GRM188R71A225KE15D; ROHS: Yes; Tolerance: 10%
C19 = CAP_NP: CAP CER 10UF 16V 10% X5R 0805; AGILE_PN: 150-75283; CAD_APPROVED: Yes; FPLIST: CC0805_OV,CC0805,CC0805_CC; HEIGHT: 1.45MM; MFG_NAME01: AVX; MFG_PN01: 0805YD106KAT2A; ROHS: Yes; Tolerance: 10%
C20 = CAP_NP: CAP CER 0.10UF 25V 10% X7R 0603; AGILE_PN: 150-75016; CAD_APPROVED: Yes; FPLIST: CC0603_OV,CC0603,0603_CC; HEIGHT: 0.97 MM; MFG_NAME01: KEMET; MFG_PN01: C0603C104K3RAC; ROHS: Yes; TOL: 10%; Tolerance: 10%
C21 C28 = CAP_NP: CAP CER 18PF 50V 5% C0G 0603; AGILE_PN: 150-75116; ASSY_OPT: DNP; CAD_APPROVED: Yes; FPLIST: CC0603_OV,CC0603,0603_CC; HEIGHT: 0.90MM; MFG_NAME01: YAGEO AMERICA; MFG_PN01: CC0603JRNPO9BN180; ROHS: Yes; Tolerance: 5%
C41 C48 = CAP_NP: CAP CER 27PF 50V 5% C0G 0402; AGILE_PN: 150-30109; CAD_APPROVED: Yes; FPLIST: CC0402_25,CC0402_HD,0402_CC; HEIGHT: .55mm; MFG_NAME01: KEMET; MFG_PN01: C0402C270J5GAC; ROHS: Yes; Tolerance: 5%
C6 C11 C12 C27 C35 C39 C49 = CAP_NP: CAP CER 10UF 16V 10% X5R 0805; AGILE_PN: 150-75283; CAD_APPROVED: Yes; FPLIST: CC0805_OV,CC0805,0805_CC; HEIGHT: 1.45MM; MFG_NAME01: AVX; MFG_PN01: 0805YD106KAT2A; ROHS: Yes; Tolerance: 10%
D6 D9 = BAT721B: DIODE SCH DUAL CC 200MA 30V SOT23; AGILE_PN: 480-77944; CAD_APPROVED: Yes; HEIGHT: 1.3MM; MFG_NAME01: Fairchild; ROHS: Yes
L1 L4 L6-L8 = IND: IND FER BEAD 100 OHM@100MHZ 1A 25% 0603; AGILE_PN: 180-75495; CAD_APPROVED: Yes; FPLIST: IND_0603,0603_CC; HEIGHT: 0.8MM; MFG_NAME01: TDK; MFG_PN01: MPZ1608D101B; PART_TYPE: Inductor; ROHS: Yes; Tolerance: 25%
L5 = BEAD_FERRITE: IND FER BEAD 120OHM@100MHZ 2A 25% 0603; AGILE_PN: 180-30008; CAD_APPROVED: Yes; FPLIST: IND_0603,IND0603_CC; HEIGHT: 0.95MM; MFG_NAME01: MURATA; MFG_PN01: BLM18PG121SH1; PART_TYPE: FERRITE; ROHS: Yes; Tolerance: 25%
R25 = RES: RES MF ZERO OHM 1/8W -- 0805; AGILE_PN: 470-75442; ASSY_OPT: DNP; CAD_APPROVED: Yes; FPLIST: RC0805_OV,RC0805,0805_CC; MFG_NAME01: YAGEO AMERICA; MFG_PN01: RC0805JR-070RL; ROHS: Yes; Tolerance: 5%
R94 = RES: RES MF 68 OHM 1/16W 1% 0402; AGILE_PN: 470-30724; CAD_APPROVED: Yes; FPLIST: RC0402_25,RC0402_HD,0402_CC; MFG_NAME01: KOA SPEER; MFG_PN01: RK73H1ETTP68R0F; ROHS: Yes; Tolerance: 1%
R78 R133 = RES: RES MF 10M  1/16W 1% 0402; AGILE_PN: 470-31288; CAD_APPROVED: Yes; FPLIST: RC0402_25,RC0402_HD,0402_CC; MFG_NAME01: KOA SPEER; MFG_PN01: RK73H1ETTP1005F; ROHS: Yes; Tolerance: 1%
TP8 TP13 TP14 TP16 TP18 TP19 TP21 = TestLoop: TEST POINT PAD 40MIL DIA SMT, NO PART TO ORDER; AGILE_PN: 211-76643; CAD_APPROVED: Yes; HEIGHT: 0.1MM; MFG_NAME01: NOTACOMPONENT; MFG_PN01: NOTACOMPONENT; ROHS: Yes
U1 = K60_LQ_LQFP_144P: IC MCU 1MB FLASH 120MHZ 1.71-3.6V LQFP144; AGILE_PN: 344-01230; CAD_APPROVED: Yes; HEIGHT: 1.6MM; MFG_NAME01: FREESCALE SEMICONDUCTOR; ROHS: Yes
Y1 = CLKGEN-SM: OSC 50MHZ FIXED 3.3V SMT; AGILE_PN: 230-76894; CAD_APPROVED: Yes; HEIGHT: 1.75MM; MFG_NAME01: ECS INC. INTERNATIONAL; MFG_PN01: ECS-3953M-500-BN; ROHS: Yes
Y2 = XTAL: XTAL 32.768KHZ PAR 20PPM -- SMT; AGILE_PN: 230-30001; CAD_APPROVED: Yes; HEIGHT: 2.25MM; MFG_NAME01: Citizen; MFG_PN01: CMR200T32.768KDZF-UT; ROHS: Yes
Y5 = CRYSTAL_JXS63: XTAL 12MHZ 20PF 30PPM -- SMT; AGILE_PN: 230-77798; CAD_APPROVED: Yes; HEIGHT: 0.75MM; MFG_NAME01: PERICOM SEMICONDUCTOR; MFG_PN01: FL1200050; ROHS: Yes
C8 C10 = CAP_NP: CAP CER 18PF 50V 5% C0G 0603; AGILE_PN: 150-75116; CAD_APPROVED: Yes; FPLIST: CC0603_OV,CC0603,0603_CC; HEIGHT: 0.90MM; MFG_NAME01: YAGEO AMERICA; MFG_PN01: CC0603JRNPO9BN180; ROHS: Yes; Tolerance: 5%
C43 = CAP_NP: CAP CER 1000PF 50V 10% X7R 0805; AGILE_PN: 150-75208; CAD_APPROVED: Yes; FPLIST: CC0805_OV,CC0805,0805_CC; HEIGHT: 0.94MM; MFG_NAME01: AVX; MFG_PN01: 08055C102KAT2A; ROHS: Yes; Tolerance: 10%
D2 = LED: LED ULTRA BRIGHT ORANGE 20MA 2V SMT 0603; AGILE_PN: 370-75080; CAD_APPROVED: Yes; HEIGHT: 0.8MM; MFG_NAME01: LITE ON; MFG_PN01: LTST-C190KFKT; ROHS: Yes
D3 = LED: LED ULTRA-BRIGHT YELLOW 30MA 5V SMT 0603; AGILE_PN: 370-75076; CAD_APPROVED: Yes; HEIGHT: 0.8MM; Label: TPWR; MFG_NAME01: LITE ON; MFG_PN01: LTST-C190KSKT; ROHS: Yes
D4 = LED: LED YEL/GRN SGL 25MA SMD 0603; AGILE_PN: 370-76537; CAD_APPROVED: Yes; HEIGHT: 0.8MM; Label: STATUS; MFG_NAME01: DIALIGHT; MFG_PN01: 598-8060-107F; ROHS: Yes
D5 = LED: LED YEL/GRN SGL 25MA SMD 0603; AGILE_PN: 370-76537; CAD_APPROVED: Yes; HEIGHT: 0.8MM; MFG_NAME01: DIALIGHT; MFG_PN01: 598-8060-107F; ROHS: Yes
D10 = DIODE_SCHTKY: DIODE SCH 1A 20V MICROSMP SMT; AGILE_PN: 480-76978; CAD_APPROVED: Yes; HEIGHT: 0.73MM; MFG_NAME01: VISHAY INTERTECHNOLOGY; MFG_PN01: MSS1P3L-M3/89A; ROHS: Yes
J11 = CONN_HDR_19: HDR 19P SMT 1.27MM SP 285H AU; AGILE_PN: 211-79023; CAD_APPROVED: Yes; HEIGHT: 7.3MM; MFG_NAME01: SAMTEC; MFG_PN01: ASP-159234-02; ROHS: Yes
J13 = USB_MINI_B_SKT: CON 1X5 USB MINI-B RA SHLD SKT  SMT 0.8MM SP 159H AU; AGILE_PN: 211-77581; CAD_APPROVED: Yes; FPLIST: con5_usb_mini_a_smt,con_usb_5m_32_sm_cust; HEIGHT: 4.05MM; MFG_NAME01: Molex; MFG_PN01: 67503-1020; ROHS: Yes
J14 = CONN_HDR_3X2: HDR 2X3 SMT 100MIL CTR 380H AU; AGILE_PN: 211-75026-00; CAD_APPROVED: Yes; HEIGHT: 9.65MM; MFG_NAME01: SAMTEC; MFG_PN01: TSM-103-01-S-DV-P-TR; ROHS: Yes
L2 L3 = BEAD: IND FER BEAD 330OHM@100MHZ 2.5A -- SMT; AGILE_PN: 180-30021; CAD_APPROVED: YES; HEIGHT: 1.05 MM; MFG_NAME01: TDK; MFG_PN01: MPZ2012S331A; PART_TYPE: FERRITE; ROHS: Yes; Tolerance: 25%
Q2 = NPN: TRAN NPN GEN 200MA 40V SOT-23; AGILE_PN: 480-75173; CAD_APPROVED: Yes; HEIGHT: 1.12 MM; MFG_NAME01: ON SEMICONDUCTOR; ROHS: Yes
Q3 = TRAN_NPN_RES: TRAN NPN GEN SW 100MA 50V SOT416 W/RES; AGILE_PN: 480-78123; CAD_APPROVED: Yes; HEIGHT: 0.95MM; MFG_NAME01: NXP SEMICONDUCTORS; MFG_PN01: PDTC115TE; ROHS: Yes
R15 = RES: RES MF 330 OHM 1/16W 1% 0402; AGILE_PN: 470-76465; CAD_APPROVED: Yes; FPLIST: RC0402_25,RC0402_HD,0402_CC; MFG_NAME01: VISHAY INTERTECHNOLOGY; MFG_PN01: CRCW0402330RFK; ROHS: Yes; Tolerance: 1%
R18 = RES: RES MF 270 OHM 1/16W 1% 0402; AGILE_PN: 470-30782; CAD_APPROVED: Yes; FPLIST: RC0402_25,RC0402_HD,0402_CC; MFG_NAME01: KOA SPEER; MFG_PN01: RK73H1ETTP2700F; ROHS: Yes; Tolerance: 1%
R38 R39 = RES: RES MF 1.3K  1/16W 1% 0402; AGILE_PN: 470-30847; CAD_APPROVED: Yes; FPLIST: RC0402_25,RC0402_HD,0402_CC; MFG_NAME01: KOA SPEER; MFG_PN01: RK73H1ETTP1301F; ROHS: Yes; Tolerance: 1%
R40 = RES: RES MF 4.99K  1/16W 1% 0402; AGILE_PN: 470-30913; CAD_APPROVED: Yes; FPLIST: RC0402_25,RC0402_HD,0402_CC; MFG_NAME01: KOA SPEER; MFG_PN01: RK73H1ETTP4991F; ROHS: Yes; Tolerance: 1%
R72 = RES: RES MF ZERO OHM 1/10W -- 0603; AGILE_PN: 470-75407; ASSY_OPT: DNP; CAD_APPROVED: Yes; FPLIST: RC0603_OV,RC0603,R603-X2,0603_CC; MFG_NAME01: VISHAY INTERTECHNOLOGY; MFG_PN01: CRCW06030000Z0EA; ROHS: Yes; Tolerance: 1%
R83 = RES: RES MF 2.2K 1/16W 1% 0402; AGILE_PN: 470-78359; CAD_APPROVED: Yes; FPLIST: RC0402_25,RC0402_HD,0402_CC; MFG_NAME01: KOA SPEER; MFG_PN01: RK73H1ETTP2201F; ROHS: Yes; Tolerance: 1%
TP15 TP17 = TestLoop: TEST POINT BLACK 40 MIL DRILL 180 MIL TH; AGILE_PN: 210-75683; CAD_APPROVED: Yes; HEIGHT: 4.8mm; MFG_NAME01: COMPONENTS CORPORATION; MFG_PN01: TP-105-01-00; ROHS: Yes
U2 = MIC2526_8P: IC LIN SW PWR ACTIVE HIGH DUAL 2.7V-5.5V 0.5A SOIC8; AGILE_PN: 312-75936; CAD_APPROVED: Yes; HEIGHT: 1.73mm; MFG_NAME01: MICREL; ROHS: Yes
U3 = LT1129CST-3.3: IC VREG LDO 3.3V 0.4A 2-26V SOT-223; AGILE_PN: 315-79125; CAD_APPROVED: Yes; HEIGHT: 1.8MM; MFG_NAME01: Micrel; ROHS: Yes
U4 = 74_04: IC GATE HEX INV -- TSSOP14; AGILE_PN: 312-75336; CAD_APPROVED: Yes; HEIGHT: 1.2MM; MFG_NAME01: TEXAS INSTRUMENTS; MFG_PN01: SN74LVC04APWE4_; ROHS: Yes
U6 = 74-125_14P: IC BUF QUAD TS 4.5-5.5V SOIC14; AGILE_PN: 312-79586; CAD_APPROVED: Yes; HEIGHT: 1.75MM; MFG_NAME01: Texas Instruments; MFG_PN01: SN74HCT125D; ROHS: Yes
U7 = SPB0503: DIODE TVS ARRAY 3CH -- 5V 0.225W SOT143; AGILE_PN: 480-76886; CAD_APPROVED: Yes; HEIGHT: 1.22MM; MFG_NAME01: LITTELFUSE; MFG_PN01: SP0503BAHTG; ROHS: Yes
U8 = MC9S08JM60CFGE: IC MCU 8BIT 60K FLASH 48MHZ 2.7-5.5V LQFP44; AGILE_PN: 312-77275; CAD_APPROVED: Yes; HEIGHT: 1.60 MM; MFG_NAME01: FREESCALE SEMICONDUCTOR; ROHS: Yes
U9 = 74LVC125: IC BUF QUAD TS 1.65-3.6V TSSOP14; AGILE_PN: 312-77298; CAD_APPROVED: Yes; HEIGHT: 1.2MM; MFG_NAME01: TEXAS INSTRUMENTS; MFG_PN01: SN74LVC125APWG4; ROHS: Yes
Y3 = XTAL: XTAL 4MHZ -- SMT; AGILE_PN: 230-76633; CAD_APPROVED: Yes; HEIGHT: 4.3MM; MFG_NAME01: ECS INC. INTERNATIONAL; MFG_PN01: ECS-40-20-5PX-TR; ROHS: Yes

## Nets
5V_EN: R84.2 U2.1(ENA) U8.23(PTB0/MISO2/ADP0)
5V_FAULT: U2.3(\\~{FLGB}) U8.21(PTG0/KBIP0)
GND: BT1.3(neg) C1.2 C2.2 C3.2 C4.2 C5.2 C6.2 C7.2 C8.2 C9.2 C10.2 C11.2 C12.2 C13.2 C14.2 C15.2 C16.2 C17.2 C18.2 C19.2 C20.2 C21.1 C23.2 C27.2 C28.1 C30.2 C31.2 C32.1 C33.2 C34.2 C35.2 C36.2 C37.2 C38.2 C39.2 C40.2 C41.2 C42.2 C43.2 C44.2 C45.2 C46.2 C47.2 C48.2 C49.2 C50.2 C51.2 C82.2 C86.2 C87.2 C88.2 D5.C(CATHODE) J3.19(A10) J4.3(A2) J4.15(A8) J4.16(B8) J4.19(A10) J5.1(A1) J5.2(B1) J5.5(A3) J5.6(B3) J5.7(A4) J5.8(B4) J5.13(A7) J5.14(B7) J10.2 J11.3(A2) J11.5(A3) J11.15(A8) J11.17(A9) J11.19(A10) J13.5(GND1) J14.2(B1) J15.6(VSS1) J15.10(CD_COMMON) J15.11(VSS2) J15.12(VSS3) J15.13(VSS4) J15.14(VSS5) L3.2 L4.2 Q1.1(EMITTER) Q2.2(EMITTER) Q3.2(EMITTER) R12.2 R21.2 R30.2 R33.2 R34.2 R38.2 R39.2 R52.3(B) R69.2 R70.2 R73.2 R82.1 R84.1 R90.2 SW1.3 SW1.4 SW2.3 SW2.4 SW3.1 SW3.2 TP15.1(Pin1) TP17.1(Pin1) U1.6(VSS1) U1.17(VSS2) U1.18(VSSUSB) U1.44(VSS3) U1.57(VSS4) U1.71(VSS5) U1.93(VSS6) U1.107(VSS7) U1.121(VSS8) U1.134(VSS9) U2.6(GND) U3.2(GND) U3.4(TAB) U4.7(GND) U5.5(GND1) U5.10(GND2) U5.12(GND3) U6.7(GND) U7.1(ANODE) U8.17(VSS1) U8.32(VSSAD/VREFL) U8.39(VSSOSC) U9.7(GND) U14.13(VSS1) U14.25(VSS2) U14.36(VSS3) U14.48(VSS4) Y1.2(GND) Y5.2(GND1) Y5.4(GND2) ; also on sheet 6
P3V3: C1.1 C3.1 C13.1 C33.1 C34.1 C35.1 C37.1 C38.1 C39.1 C47.1 C82.1 C86.1 C87.1 C88.1 D9.2 J3.2(B1) J4.2(B1) J8.2 J15.4(VDD) L5.2 R13.1 R15.1 R18.1 R19.1 R20.1 R26.1 R27.2 R28.1 R29.1 R36.1 R52.1(A) R53.1 R54.1 R55.1 R56.1 R58.2 R64.2 R67.2 R75.1 R77.2 R79.1 R89.1 R99.1 R118.2 R128.2 R313.1 TP18.1(Pin1) U3.3(OUTPUT) U4.14(VCC) U5.14(VDD) U9.14(VCC) U14.12(VCC1) U14.34(VCC2) U14.37(VCC3) U14.39(VCC4) ; also on sheet 6
P3V3_MCU: C4.1 C17.1 C18.1 C23.1 C30.1 C31.1 C49.1 C50.1 C51.1 D6.2 J9.1 J11.1(A1) L1.2 L6.2 R25.2 R71.1 TP13.1(Pin1) U1.5(VDD1) U1.16(VDD2) U1.43(VDD3) U1.56(VDD4) U1.70(VDD5) U1.94(VDD6) U1.108(VDD7) U1.122(VDD8) U1.135(VDD9)
P3V3R: J8.1 L1.1
P5V_ELEV: D10.C ; also on sheet 6
P5V_SW: C6.1 C44.1 D9.3 R80.1 TP14.1(Pin1) U6.14(VCC)
P5V_TRG_USB: C27.1 D10.A J3.1(A1) J4.1(A1) J12.2 TP8.1(Pin1) U2.5(OUTB) U3.1(VIN)
P5V_USB: C9.1 C11.1 C15.1 D3.A(ANODE) D4.A(ANODE) J14.6(B3) L2.2 R31.1 R32.1 R35.1 R37.1 R76.1 R81.1 TP19.1(Pin1) U2.7(IN) U8.16(VDD1) U8.31(VDDAD/VREFH)
VBAT: C5.1 J9.2 U1.42(VBAT)
VBATD: D6.3 J9.3
VDD_OSC: J18.2 Y1.4(VDD)
VDDA: C22.1 C24.1 J3.4(B2) J4.4(B2) L6.1 L8.2 U1.31(VDDA) ; also on sheet 6
VSSA: C22.2 C24.2 J3.6(B3) J4.5(A3) J4.6(B3) J4.7(A4) J4.10(B5) J4.11(A6) J4.13(A7) J4.14(B7) L4.1 L7.2 U1.34(VSSA) ; also on sheet 6
50MHz_OSC: J6.1 R94.1
+3_3V_OSC_33M: C19.1 C20.1 J18.1 L5.1
ACC_BYP: C40.1 U5.2(BYP)
ACC_SA0: R89.2 R90.1 U5.7(SA0)
ADC0_DM0: J4.9(A5) U1.28(PGA0_DM/ADC0_DM0/ADC1_DM3) ; also on sheet 6
ADC0_DM1: J4.18(B9) R20.2 U1.24(PGA2_DM/ADC2_DM0/ADC3_DM3/ADC0_DM1)
ADC0_DP0: J4.8(B4) U1.27(PGA0_DP/ADC0_DP0/ADC1_DP3) ; also on sheet 6
ADC0_DP1: J4.17(A9) R19.2 U1.23(PGA2_DP/ADC2_DP0/ADC3_DP3/ADC0_DP1)
ADC0_SE16: R21.1 R24.2 U1.36(ADC0_SE16/ADC0_SE21/CMP1_IN2)
ADC1_DM0: U1.30(PGA1_DM/ADC1_DM0/ADC0_DM3) ; also on sheet 6
ADC1_DM1: J19.1 U1.26(PGA3_DM/ADC3_DM0/ADC2_DM3/ADC1_DM1)
ADC1_DP0: J4.12(B6) U1.29(PGA1_DP/ADC1_DP0/ADC0_DP3) ; also on sheet 6
ADC1_DP1: J3.17(A9) R56.2 U1.25(PGA3_DP/ADC3_DP0/ADC2_DP3/ADC1_DP1)
ADC1_SE16: J3.18(B9) R53.2 U1.35(ADC1_SE16/ADC0_SE22/CMP2_IN2)
BRD_ID0: R39.1 R81.2 U8.25(PTB2/SPSCK2/ADP2)
BRD_ID1: R37.2 R38.1 U8.27(PTB4/KBIP4/ADP4)
BRD_REV0: R30.1 R31.2 U8.40(PTC0/SCL)
BRD_REV1: R32.2 R33.1 U8.41(PTC1/SDA)
BRD_REV2: R34.1 R35.2 U8.42(PTC2)
BRDG_RXD: R65.1 U9.3(1Y)
BRDG_TXD: R63.1 R79.2 U6.9(3A)
BRK_TMS: U8.26(PTB3/~{SS2}/ADP3) U9.5(2A)
CD_SW: J15.9(CD_SW) R132.2
CLKIN0: J6.3 ; also on sheet 6
CMP0_IN0: C2.1 J16.2 R14.2
DAC0_OUT: U1.38(DAC0_OUT/ADC0_SE23/CMP1_IN3) ; also on sheet 6
DAC1_OUT: U1.39(DAC1_OUT/ADC1_SE23/CMP2_IN3) ; also on sheet 6
DIN: U6.3(1Y) U8.12(PTE4/MISO1)
DOUT: U8.13(PTE5/MOSI1) U9.9(3A)
ELE_PS_B: Q3.3(COLLECTOR) R83.2 U2.4(ENB)
ELE_PS_SENSE: Q3.1(BASE) ; also on sheet 6
EXTAL1: C48.1 R133.2 U1.45(PTE24/ADC0_SE17/EXTAL1/CAN1_TX/UART4_TX/I2S1_TX_FS/~{EWM_OUT}/I2S1_RXD1) Y5.3
EXTAL32_RTC: C21.2 U1.41(EXTAL32) Y2.1
EXTAL_MAIN: J6.2 U1.72(PTA18/EXTAL/FTM0_FLT2/FTM_CLKIN0)
EZP_CSR_B: J11.9(A5) R72.2
I2S0_RX_BCLK/I2S0_TXD1: J23.2 ; also on sheet 6
I2S0_RX_FS/I2S0_RXD1: J24.2 ; also on sheet 6
I2S0_TX_FS: J22.2 ; also on sheet 6
I2S0_TXD0: J21.2 ; also on sheet 6
IRDA_SEN: Q1.2(COLLECTOR) R13.2 R14.1
IRDAJ: D1.A(ANODE) J2.1
IRDAR: D1.C(CATHODE) R12.1
JM60_DN: R42.2 U8.18(USBDN)
JM60_DP: R41.2 U8.19(USBDP)
JM60_EXTAL: C8.1 R78.2 U8.38(PTG5/EXTAL) Y3.2
JM60_IRQ_B: J10.1 U8.2(IRQ/TPMCLK)
JM60_RESET_B: C43.1 J14.4(B2) R76.2 U8.3(RESET)
JM60_XTAL: C10.1 R78.1 U8.37(PTG4/XTAL) Y3.1
JM_BKGD: J14.1(A1) U8.36(BKGD/MS)
LED2R: D12.A(ANODE) R77.1
LEDGR: D11.A(ANODE) R67.1
LEDOR: D7.A(ANODE) R58.1
LEDYR: D8.A(ANODE) R64.1
NFC_CE_B: R130.1 U14.9(~{CE})
NFC_D9: R103.1 U14.27(I/O9)
NFC_D10: R102.1 U14.28(I/O10)
NFC_D11: R101.1 U14.33(I/O11)
NFC_R/B_N: R91.2 R118.1 U14.7(R/~{B})
NFC_WE: R100.2 U14.18(~{WE})
NFC_WP_B: R128.1 U14.19(~{WP})
OUT_EN: R70.1 U4.3(IB) U8.15(PTE7/~{SS1})
OUT_EN_B: U4.4(OB) U6.1(~{OE1}) U6.4(~{OE2}) U9.4(~{2OE}) U9.10(~{3OE}) U9.13(~{4OE})
POT_IN: C45.1 J19.2 R52.2(WIPER)
PTA0: J11.4(B2) U1.50(PTA0/TSI0_CH1/~{UART0_CTS}/~{UART0_COL}/FTM0_CH5/JTAG_TCLK/SWD_CLK/EZP_CLK) U9.11(4Y)
PTA1: J11.8(B4) U1.51(PTA1/TSI0_CH2/UART0_RX/FTM0_CH6/JTAG_TDI/EZP_DI) U9.8(3Y) ; also on sheet 6
PTA2: J11.6(B3) U1.52(PTA2/TSI0_CH3/UART0_TX/FTM0_CH7/JTAG_TDO/TRACE_SWO/EZP_DO) U6.2(1A) ; also on sheet 6
PTA3: J11.2(B1) R27.1 U1.53(PTA3/TSI0_CH4/~{UART0_RTS}/FTM0_CH0/JTAG_TMS/SWD_DIO) U9.6(2Y)
PTA4: J3.12(B6) R57.1 R72.1 U1.54(PTA4/TSI0_CH5/FTM0_CH1/~{NMI}/~{EZP_CS})
PTA4R: D7.1(Electrode) R57.2
PTA5: U1.55(PTA5/USB_CLKIN/FTM0_CH2/RMII0_RXER/MII0_RXER/~{JTAG_TRST}/CMP2_OUT/I2S0_TX_BCLK) ; also on sheet 6
PTA6: R98.2 U1.58(PTA6/ADC3_SE6A/ULPI_CLK/FTM0_CH3/I2S1_RXD0/TRACE_CLKOUT) ; also on sheet 6
PTA7: J11.20(B10) U1.59(PTA7/ADC0_SE10/ULPI_DIR/FTM0_CH4/I2S1_RX_BCLK/TRACE_D3) ; also on sheet 6
PTA8: J11.18(B9) U1.60(PTA8/ADC0_SE11/ULPI_NXT/FTM1_CH0/I2S1_RX_FS/FTM1_QD_PHA/TRACE_D2) ; also on sheet 6
PTA9: J11.16(B8) U1.61(PTA9/ADC3_SE5A/ULPI_STP/FTM1_CH1/MII0_RXD3/FTM1_QD_PHB/TRACE_D1) ; also on sheet 6
PTA10: D12.C(CATHODE) J11.14(B7) U1.62(PTA10/ADC3_SE4A/ULPI_DATA0/FTM2_CH0/MII0_RXD2/FTM2_QD_PHA/TRACE_D0) ; also on sheet 6
PTA11: D7.C(CATHODE) U1.63(PTA11/ADC3_SE15/ULPI_DATA1/FTM2_CH1/MII0_RXCLK/FTM2_QD_PHB) ; also on sheet 6
PTA12: J21.1 U1.64(PTA12/CAN0_TX/FTM1_CH0/RMII0_RXD1/MII0_RXD1/FTM1_QD_PHA/CMP2_IN0/I2S0_TXD0) ; also on sheet 6
PTA13: J22.1 U1.65(PTA13/CAN0_RX/FTM1_CH1/RMII0_RXD0/MII0_RXD0/FTM1_QD_PHB/CMP2_IN1/I2S0_TX_FS) ; also on sheet 6
PTA14: J23.1 U1.66(PTA14/CMP3_IN0/SPI0_PCS0/UART0_TX/RMII0_CRS_DV/MII0_RXDV/I2S0_RX_BCLK/I2S0_TXD1) ; also on sheet 6
PTA15: U1.67(PTA15/CMP3_IN1/SPI0_SCK/UART0_RX/RMII0_TXEN/MII0_TXEN/I2S0_RXD0) ; also on sheet 6
PTA16: J24.1 U1.68(PTA16/CMP3_IN2/SPI0_SOUT/~{UART0_CTS}/~{UART0_COL}/RMII0_TXD0/MII0_TXD0/I2S0_RX_FS/I2S0_RXD1) ; also on sheet 6
PTA17: U1.69(PTA17/ADC1_SE17/SPI0_SIN/~{UART0_RTS}/RMII0_TXD1/MII0_TXD1/I2S0_MCLK) ; also on sheet 6
PTA19: J5.18(B9) SW1.1 SW1.2 U1.73(PTA19/XTAL/FTM1_FLT0/FTM_CLKIN1/LPTMR0_ALT1)
PTA24: U1.75(PTA24/CMP3_IN4/ULPI_DATA2/MII0_TXD2/FB_A29) ; also on sheet 6
PTA25: U1.76(PTA25/CMP3_IN5/ULPI_DATA3/MII0_TXCLK/FB_A28) ; also on sheet 6
PTA26: U1.77(PTA26/ADC2_SE15/ULPI_DATA4/MII0_TXD3/FB_A27) ; also on sheet 6
PTA27: U1.78(PTA27/ADC2_SE14/ULPI_DATA5/MII0_CRS/FB_A26) ; also on sheet 6
PTA28: D8.C(CATHODE) U1.79(PTA28/ADC2_SE13/ULPI_DATA6/MII0_TXER/FB_A25) ; also on sheet 6
PTA29: D11.C(CATHODE) U1.80(PTA29/ADC2_SE12/ULPI_DATA7/MII0_COL/FB_A24) ; also on sheet 6
PTB0: J3.3(A2) U1.81(PTB0/ADC0/1/2/3_SE8/TSI0_WU/I2C0_SCL/FTM1_CH0/RMII0_MDIO/MII0_MDIO/FTM1_QD_PHA) ; also on sheet 6
PTB1: J3.5(A3) U1.82(PTB1/ADC0/1/2/3_SE9/TSI0_CH6/I2C0_SDA/FTM1_CH1/RMII0_MDC/MII0_MDC/FTM1_QD_PHB) ; also on sheet 6
PTB2: J3.7(A4) R66.1 U1.83(PTB2/ADC0_SE12/TSI0_CH7/I2C0_SCL/~{UART0_RTS}/ENET0_1588_TMR0/FTM0_FLT3)
PTB2R: D11.1(Electrode) R66.2
PTB3: J3.8(B4) R59.1 U1.84(PTB3/ADC0_SE13/TSI0_CH8/I2C0_SDA/~{UART0_CTS}/~{UART0_COL}/ENET0_1588_TMR1/FTM0_FLT0)
PTB3R: D8.1(Electrode) R59.2
PTB4: U1.85(PTB4/ADC1_SE10/ENET0_1588_TMR2/FTM1_FLT0) U5.11(INT1) ; also on sheet 6
PTB5: U1.86(PTB5/ADC1_SE11/ENET0_1588_TMR3/FTM2_FLT0) ; also on sheet 6
PTB6: U1.87(PTB6/ADC1_SE12/FB_AD23) ; also on sheet 6
PTB7: U1.88(PTB7/ADC1_SE13/FB_AD22) U5.9(INT2) ; also on sheet 6
PTB8: J5.16(B8) U1.89(PTB8/~{UART3_RTS}/FB_AD21) ; also on sheet 6
PTB9: J5.17(A9) U1.90(PTB9/SPI1_PCS1/~{UART3_CTS}/FB_AD20) ; also on sheet 6
PTB10: U1.91(PTB10/ADC1_SE14/SPI1_PCS0/UART3_RX/I2S1_TX_BCLK/FB_AD19/FTM0_FLT1) ; also on sheet 6
PTB11: U1.92(PTB11/ADC1_SE15/SPI1_SCK/UART3_TX/I2S1_TX_FS/FB_AD18/FTM0_FLT2) ; also on sheet 6
PTB16: J3.13(A7) R68.1 U1.95(PTB16/TSI0_CH9/SPI1_SOUT/UART0_RX/I2S1_TXD0/FB_AD17/EWM_IN) ; also on sheet 6
PTB16R: D12.1(Electrode) R68.2
PTB17: J3.14(B7) U1.96(PTB17/TSI0_CH10/SPI1_SIN/UART0_TX/I2S1_TXD1/FB_AD16/~{EWM_OUT}) ; also on sheet 6
PTB18: J3.15(A8) U1.97(PTB18/TSI0_CH11/CAN0_TX/FTM2_CH0/FB_AD15/FTM2_QD_PHA/I2S0_TX_BCLK) ; also on sheet 6
PTB19: J3.16(B8) U1.98(PTB19/TSI0_CH12/CAN0_RX/FTM2_CH1/~{FB_OE}/FTM2_QD_PHB/I2S0_TX_FS) ; also on sheet 6
PTB20: U1.99(PTB20/ADC2_SE4A/SPI2_PCS0/FB_AD31/NFC_DATA15/CMP0_OUT) U14.47(I/O15) ; also on sheet 6
PTB21: U1.100(PTB21/ADC2_SE5A/SPI2_SCK/FB_AD30/NFC_DATA14/CMP1_OUT) U14.46(I/O14) ; also on sheet 6
PTB22: U1.101(PTB22/SPI2_SOUT/FB_AD29/NFC_DATA13/CMP2_OUT) U14.45(I/O13) ; also on sheet 6
PTB23: U1.102(PTB23/SPI2_SIN/SPI0_PCS5/FB_AD28/NFC_DATA12/CMP3_OUT) U14.40(I/O12) ; also on sheet 6
PTC0: J3.9(A5) J23.3 R101.2 U1.103(PTC0/ADC0_SE14/TSI0_CH13/SPI0_PCS4/PDB0_EXTRG/FB_AD14/NFC_DATA11/I2S0_TXD1) ; also on sheet 6
PTC1: J3.10(B5) J21.3 R102.2 U1.104(PTC1/ADC0_SE15/TSI0_CH14/SPI0_PCS3/~{UART1_RTS}/FTM0_CH0/FB_AD13/NFC_DATA10/I2S0_TXD0) ; also on sheet 6
PTC2: J3.11(A6) J22.3 R103.2 U1.105(PTC2/ADC0_SE4B/TSI0_CH15/SPI0_PCS2/~{UART1_CTS}/FTM0_CH1/FB_AD12/NFC_DATA9/I2S0_TX_FS/CMP1_IN0) ; also on sheet 6
PTC3: U1.106(PTC3/SPI0_PCS1/UART1_RX/FTM0_CH2/FB_CLKOUT/I2S0_TX_BCLK/CMP1_IN1) ; also on sheet 6
PTC4: U1.109(PTC4/SPI0_PCS0/UART1_TX/FTM0_CH3/FB_AD11/NFC_DATA8/I2S1_TX_BCLK/CMP1_OUT) U14.26(I/O8) ; also on sheet 6
PTC5: U1.110(PTC5/SPI0_SCK/LPTMR0_ALT2/FB_AD10/NFC_DATA7/CMP0_OUT/I2S1_TX_FS/I2S0_RXD0) U14.44(I/O7) ; also on sheet 6
PTC6: J16.1 U1.111(PTC6/CMP0_IN0/SPI0_SOUT/PDB0_EXTRG/FB_AD9/NFC_DATA6/I2S0_MCLK/I2S0_RX_BCLK) U14.43(I/O6) ; also on sheet 6
PTC7: U1.112(PTC7/CMP0_IN1/SPI0_SIN/USB_SOF_OUT/FB_AD8/NFC_DATA5/I2S0_RX_FS) U14.42(I/O5) ; also on sheet 6
PTC8: U1.113(PTC8/ADC1_SE4B/CMP0_IN2/FTM3_CH4/FB_AD7/NFC_DATA4/I2S0_MCLK) U14.41(I/O4) ; also on sheet 6
PTC9: U1.114(PTC9/ADC1_SE5B/CMP0_IN3/FTM3_CH5/FB_AD6/NFC_DATA3/FTM2_FLT0/I2S0_RX_BCLK) U14.32(I/O3) ; also on sheet 6
PTC10: U1.115(PTC10/ADC1_SE6B/I2C1_SCL/FTM3_CH6/FB_AD5/NFC_DATA2/I2S1_MCLK/I2S0_RX_FS) U14.31(I/O2) ; also on sheet 6
PTC11: J24.3 R100.1 U1.116(PTC11/ADC1_SE7B/I2C1_SDA/FTM3_CH7/~{FB_RW}/NFC_WE/I2S0_RXD1) ; also on sheet 6
PTC12: U1.117(PTC12/~{UART4_RTS}/FB_AD27/FTM3_FLT0) ; also on sheet 6
PTC13: U1.118(PTC13/~{UART4_CTS}/FB_AD26) ; also on sheet 6
PTC14: U1.119(PTC14/UART4_RX/FB_AD25) ; also on sheet 6
PTC15: U1.120(PTC15/UART4_TX/FB_AD24) ; also on sheet 6
PTC16: R91.1 U1.123(PTC16/CAN1_RX/UART3_RX/ENET0_1588_TMR0/~{FB_CS5}/FB_TSIZ1/~{FB_BE23_16_BLS15_8}/NFC_RB) ; also on sheet 6
PTC17: R130.2 U1.124(PTC17/CAN1_TX/UART3_TX/ENET0_1588_TMR1/~{FB_CS4}/FB_TSIZ0/~{FB_BE31_24_BLS7_0}/~{NFC_CE0}) ; also on sheet 6
PTD0: U1.127(PTD0/SPI0_PCS0/~{UART2_RTS}/FTM3_CH0/FB_ALE/~{FB_CS1}/~{FB_TS}/I2S1_RXD1) ; also on sheet 6
PTD1: U1.128(PTD1/ADC0_SE5B/SPI0_SCK/~{UART2_CTS}/FTM3_CH1/~{FB_CS0}/I2S1_RXD0) ; also on sheet 6
PTD2: U1.129(PTD2/SPI0_SOUT/UART2_RX/FTM3_CH2/FB_AD4/I2S1_RX_FS) ; also on sheet 6
PTD3: U1.130(PTD3/SPI0_SIN/UART2_TX/FTM3_CH3/FB_AD3/I2S1_RX_BCLK) ; also on sheet 6
PTD4: U1.131(PTD4/SPI0_PCS1/~{UART0_RTS}/FTM0_CH4/FB_AD2/NFC_DATA1/EWM_IN) U14.30(I/O1) ; also on sheet 6
PTD5: U1.132(PTD5/ADC0_SE6B/SPI0_PCS2/~{UART0_CTS}/~{UART0_COL}/FTM0_CH5/FB_AD1/NFC_DATA0/~{EWM_OUT}) U14.29(I/O0) ; also on sheet 6
PTD6: U1.133(PTD6/ADC0_SE7B/SPI0_PCS3/UART0_RX/FTM0_CH6/FB_AD0/FTM0_FLT0) ; also on sheet 6
PTD7: J2.2 U1.136(PTD7/CMT_IRO/UART0_TX/FTM0_CH7/FTM0_FLT1)
PTD8: J5.3(A2) R54.2 U1.137(PTD8/I2C0_SCL/UART5_RX/FB_A16/NFC_CLE) U5.4(SCL) U14.16(CLE) ; also on sheet 6
PTD9: J5.4(B2) R55.2 U1.138(PTD9/I2C0_SDA/UART5_TX/FB_A17/NFC_ALE) U5.6(SDA) U14.17(ALE) ; also on sheet 6
PTD10: J5.15(A8) U1.139(PTD10/~{UART5_RTS}/FB_A18/NFC_RE) U14.8(~{RE})
PTD11: U1.140(PTD11/SPI2_PCS0/~{UART5_CTS}/SDHC0_CLKIN/FB_A19) ; also on sheet 6
PTD12: J5.12(B6) U1.141(PTD12/SPI2_SCK/FTM3_FLT0/SDHC0_D4/FB_A20) ; also on sheet 6
PTD13: J5.10(B5) U1.142(PTD13/SPI2_SOUT/SDHC0_D5/FB_A21) ; also on sheet 6
PTD14: J5.9(A5) U1.143(PTD14/SPI2_SIN/SDHC0_D6/FB_A22) ; also on sheet 6
PTD15: J5.11(A6) U1.144(PTD15/SPI2_PCS1/SDHC0_D7/FB_A23) ; also on sheet 6
PTE0: J15.8(DAT1) U1.1(PTE0/ADC1_SE4A/SPI1_PCS1/UART1_TX/SDHC0_D1/I2C1_SDA/RTC_CLKOUT) ; also on sheet 6
PTE1: J15.7(DAT0) U1.2(PTE1/ADC1_SE5A/SPI1_SOUT/UART1_RX/SDHC0_D0/I2C1_SCL/SPI1_SIN) ; also on sheet 6
PTE2: J15.5(CLK) U1.3(PTE2/ADC1_SE6A/SPI1_SCK/~{UART1_CTS}/SDHC0_DCLK) ; also on sheet 6
PTE3: J15.3(CMD) R313.2 U1.4(PTE3/ADC1_SE7A/SPI1_SIN/~{UART1_RTS}/SDHC0_CMD/SPI1_SOUT) ; also on sheet 6
PTE4: J15.2(CD/DAT3) U1.7(PTE4/SPI1_PCS0/UART3_TX/SDHC0_D3) ; also on sheet 6
PTE5: J15.1(DAT2) U1.8(PTE5/SPI1_PCS2/UART3_RX/SDHC0_D2/FTM3_CH0) ; also on sheet 6
PTE6: U1.9(PTE6/SPI1_PCS3/~{UART3_CTS}/FTM3_CH1/USB_SOF_OUT/I2S0_MCLK) ; also on sheet 6
PTE7: U1.10(PTE7/~{UART3_RTS}/FTM3_CH2/I2S0_RXD0) ; also on sheet 6
PTE8: R63.2 U1.11(PTE8/ADC2_SE16/UART5_TX/FTM3_CH3/I2S0_RXD1/I2S0_RX_FS) ; also on sheet 6
PTE9: R65.2 U1.12(PTE9/ADC2_SE17/UART5_RX/FTM3_CH4/I2S0_TXD1/I2S0_RX_BCLK) ; also on sheet 6
PTE10: U1.13(PTE10/~{UART5_CTS}/FTM3_CH5/I2S0_TXD0) ; also on sheet 6
PTE11: U1.14(PTE11/ADC3_SE16/~{UART5_RTS}/FTM3_CH6/I2S0_TX_FS) ; also on sheet 6
PTE12: U1.15(PTE12/ADC3_SE17/FTM3_CH7/I2S0_TX_BCLK) ; also on sheet 6
PTE26: J5.19(A10) SW2.1 SW2.2 U1.47(PTE26/ADC3_SE5B/ENET_1588_CLKIN/~{UART4_CTS}/I2S1_TXD0/RTC_CLKOUT/USB_CLKIN) ; also on sheet 6
PTE27: U1.48(PTE27/ADC3_SE4B/~{UART4_RTS}/I2S1_MCLK) ; also on sheet 6
PTE28: R132.1 U1.49(PTE28/ADC3_SE7A) ; also on sheet 6
PU1: R80.2 U6.12(4A) U6.13(~{OE4})
PU2: R75.2 U4.1(IA)
PU3: R26.2 U4.9(ID)
PU4: R28.2 U4.11(IE)
PU5: R29.2 U4.13(IF)
PU_PO_LED: D5.A(ANODE) R18.2
PU_ST: D4.C(CATHODE) R17.2
PU_TP: D3.C(CATHODE) R16.2
R_50MHz_OSC: R94.2 Y1.3(CLKOUT)
R_P3V3: C16.1 C46.1 R99.2 U5.1(VDDIO)
R_PU_ST: R17.1 U8.30(PTD1/ADP9/ACMP-)
R_PU_TP: R16.1 U8.29(PTD0/ADP8/ACMP+)
RESET_B: C42.1 D2.C(CATHODE) J3.20(B10) J4.20(B10) J11.10(B5) Q2.3(COLLECTOR) R71.2 SW3.3 SW3.4 U1.74(~{RESET}) U6.5(2A) ; also on sheet 6
RST_BD: Q2.1(BASE) R73.1 R74.2
RSTR: D2.A(ANODE) R15.2
RTS: R69.1 U4.5(IC) U8.34(PTG2/KBIP6)
SCLK_OUT: R40.1 U8.14(PTE6/SPSCK1)
ST_USB_AB_DM: R23.2 U1.20(USB0_DM)
ST_USB_AB_DP: R22.2 U1.19(USB0_DP)
T_RXD1: U6.8(3Y) U8.9(PTE1/RxD1)
T_TXD1: U8.8(PTE0/TxD1) U9.2(1A)
TCLK_EN: R40.2 U8.11(PTE3/TPM1CH1) U9.12(4A)
TGT_PWR: J11.11(A6) J11.13(A7) J12.1
TRACE_CLKOUT: J11.12(B6) R98.1
TRESET_IN: U6.6(2Y) U8.33(PTD2/KBIP2/ACMPO)
TRESET_OUT: R74.1 U8.1(PTC4)
TXD_RXD_EN_B: U4.6(OC) U6.10(~{OE3}) U9.1(~{1OE})
USB-SHLD: J13.S1(SHLD1) J13.S2(SHLD2) J13.S3(SHLD3) J13.S4(SHLD4) L3.1
USB_AB_DM: R23.1 ; also on sheet 6
USB_AB_DP: R22.1 ; also on sheet 6
USB_DN: J13.2(D-) R42.1 U7.3(CATHODE2)
USB_DP: J13.3(D+) R41.1 U7.4(CATHODE3)
USB_PWR: D9.1 U2.8(OUTA)
USB_VBUS: J13.1(VBUS) L2.1 U7.2(CATHODE1)
VCOIN: BT1.1(pos1) BT1.2(pos2) D6.1
VOUT_3V3: C7.1 C36.1 R25.1 TP16.1(Pin1) U1.21(VOUT33)
VREF_OUT: C29.1 TP21.1(Pin1) U1.37(VREF_OUT/CMP0_IN5/ADC1_SE18/CMP1_IN5)
VREFH: C25.1 C26.1 L8.1 U1.32(VREFH)
VREFL: C25.2 C26.2 C29.2 L7.1 U1.33(VREFL)
VREGIN: C32.2 R24.1 U1.22(VREGIN) ; also on sheet 6
VTRG_EN: R82.2 R83.1 U8.24(PTB1/MOSI2/ADP1)
VTRG_FAULT: U2.2(\\~{FLGA}) U8.22(PTG1/KBIP1)
VTRG_IN: R36.2 U8.28(PTB5/KBIP5/ADP5)
VUSB3V3: C12.1 C14.1 U8.20(VUSB33)
XTAL1: C41.1 R133.1 U1.46(PTE25/ADC0_SE18/XTAL1/CAN1_RX/UART4_RX/I2S1_TX_BCLK/EWM_IN/I2S1_TXD1) Y5.1
XTAL32_RTC: C28.2 U1.40(XTAL32) Y2.2

Not connected (* = marked no-connect by the designer): J5 20(B10)*; J13 4(ID)*; J14 3(A2)* 5(A3)*; U1 125(PTC18/~{UART3_RTS}/ENET0_1588_TMR2/~{FB_TBST}/~{FB_CS2}/~{FB_BE15_8_BLS23_16}/~{NFC_CE1})* 126(PTC19/~{UART3_CTS}/ENET0_1588_TMR3/~{FB_CS3}/~{FB_BE7_0_BLS31_24}/~{FB_TA})*; U4 2(OA)* 8(OD)* 10(OE)* 12(OF)*; U5 3(NC3)* 8(NC8)* 13(NC13)* 15(NC15)* 16(NC16)*; U6 11(4Y)*; U8 4(PTF0/TPM1CH2)* 5(PTF1/TPM1CH3)* 6(PTF4/TPM2CH0)* 7(PTF5/TPM2CH1)* 10(PTE2/TPM1CH0)* 35(PTG3/KBIP7)* 43(PTC3/TxD2)* 44(PTC5/RxD2)*; U14 1(NC1)* 2(NC2)* 3(NC3)* 4(NC4)* 5(NC5)* 6(NC6)* 10(NC10)* 11(NC11)* 14(NC14)* 15(NC15)* 20(NC20)* 21(NC21)* 22(NC22)* 23(NC23)* 24(NC24)* 35(NC35)* 38(NC38)*; Y1 1(OE)*

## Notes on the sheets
sheet 1
- Default: 1-2
  (use P3V3)
- TCK
- TDI/FTM0_CH6/UART0_RX
- TDO/FTM0_CH7/UART0_TX
- TMS
- EZP_CS_N/TSI_CH5
- TRST/RMII0_RXER-MII0_RXER
- ULPI_CLK/TRACE_CLKOUT/FTM0_CH3
- ULPI_DIR/TRACE_D3/FTM0_CH4
- ULPI_NXT/TRACE_D2/FTM1_CH0
- ULPI_STP/FTM1_CH1/TRACE_D1
- ULPI_DATA0
- ULPI_DATA1
- RMII0_RXD1-MII0_RXD1/CAN_TX0
- RMII0_RXD0-MII0_RXD0/CAN_RX0
- RMII0_CRS_DV-MII0_RXDV
- RMII0_TXEN-MII0_TXEN
- RMII0_TXD0-MII0_TXD0
- RMII0_TXD1-MII0_TXD1
- EXTAL
- TWRPI_GPIO3/pushbutton1
- ULPI_DATA2
- ULPI_DATA3
- ULPI_DATA4
- ULPI_DATA5
- ULPI_DATA6
- ULPI_DATA7
- RMII0_MDIO-MII0_MDIO/TSI0_CH0
- RMII0_MDC-MII0_MDC/TSI0_CH6
- TS_TCH_I2C_SCL/TSI0_CH7
- TS_TCH_I2C_SDA/TSI_CH8
- IRQG/IRQH/ADC1_SE10
- FB_AD23/IRQC/IRQD/ADC1_SE12
- IRQE/IRQF/ADC1_SE11
- FB_AD22/IRQA/IRQB/ADC1_SE13
- FB_AD21/TWRPI_GPIO1
- Default: 1-2
  (use P3V3_MCU)
- FB_AD20/TWRPI_GPIO2
- FB_AD19
- FB_AD18
- FB_AD16/DSPI_DIN/TSI0_CH10
- FB_AD17/DSPI_DOUT/TSI_CH9
- FB_AD15/TSI0_CH11
- FB_OE_N/TSI0_CH12
- FB_AD31-NF_IO15/SPI2_PCS0
- 2016/25/32
  Coin Cell
- FB_AD30-NF_IO14/SPI2_SCLK
- FB_AD28-NF_IO12/SPI2_SIN
- FB_AD29-NF_IO13/SPI2_SOUT
- FB_AD14-NF_IO11/TSI0_CH13
- FB_AD13-NF_IO10/TSI0_CH14/FTM0_CH0
- FB_AD12-NF_IO9/FTM0_CH1/TSI0_CH15
- Plce R172 and 173 Close to pin 19
  and 20 of U1 Respectively
- FB_CLKOUT/FTM0_CH2
- FB_AD10-NF_IO7/DSPI_SCK
- FB_AD11-NF_IO8/DSPI_CS_N
- FB_AD9-NF_IO6/CMP_IN0
- FB_AD8-NF_IO5/USB_AB_ID
- FB_AD7-NF_IO4/SSI_MCLK
- FB_AD6-NF_IO3/USB_AB_VBUS_OC
- FB_AD5-NF_IO2/I2C1_SCL
- FB_AD27/UART4_RTS_B
- FB_WE/I2C1_SDA
- FB_AD26/UART4_CTS_B
- FB_AD25/UART4_RXD1
- FB_AD24/UART4_TXD1
- CAN_RX1/NFC_RnB/UART3_RXD
- CAN_TX1/NF_CE_B/UART3_TXD
- FB_CS1_B/USB_AB_VBUS_EN
- FB_CS0_B
- FB_AD4/UART2_RX
- FB_AD2-NF_IO1
- FB_AD3/IRDA_TXD
- FB_AD1-NF_IO0/FTM0_CH5
- FB_AD0/TMR2/UART0_RX
- CMT_IRO/UART0_TX
- Place Y2 and related components as close
  as possible to U1
- NFC_CLE/I2C0_SCL
- NFC_ALE/I2C0_SDA
- NFC_RE/TWRPI_GPIO0/IRQ
- SPI2_CS0
- SPI2_CLK
- SPI2_MOSI
- SPI2_MISO
- Intersheet References
- SPI2_CS1
- SDHC0_D1
- SDHC0_D0/SPI1_SIN
- SDHC0_DCLK/SPI1_SCK
- SDHC0_CMD/SPI1_SOUT
- SDHC0_D3/SPI1_PCS0
- GPIO_E6/I2S0_MCLK
- SDHC0_D2/GPIO_E5
- AUD_SDATAI/GPIO_E7
- I2S0_RX_FS/UART5_TXD
- I2S0_RX_BCLK/UART5_RXD
- AUD_SDATAO/UART5_CTS_B
- I2S0_TX_FS/UART5_RTS_B
- I2S0_TX_BCLK/GPIO_E12
- Push_Button0/RTC_CLKOUT/TWRPI_GPIO4
- GPIO_E27
- SD_Card_Detect
- Place Y5 and related
  components as close as
  possible to U1
- CLOCK Input
- Default: 1-2
  (use crystal)
sheet 2
- On Board OSBDM/Serial Bridge
- Board Rev
- Board ID
- TCK
- TDI
- TMS
- TCK/EZP_CLK
- TDO/EZP_DO
- TMS
- KEY - PIN 7
- TDI/EZP_DI
- EZP_CS_B
- UART5_RX
- TRACED0
- TRACED1
- TRACED2
- RXD Source Select
- Default: no shunt
  (Disconnect Target Power)
- TRACED3
- JTAG
- TDO
- TXD Destination Select
- UART5_TX
- Intersheet References
- RESET
- MANUAL
  RESET
- Default: no shunt
  (Disable Bootload)
- JM60
  Bootload
   Enable
- JM60 BDM
- LT1129-3.3V
- POWER ON
sheet 3
- MICRO SD INTERFACE
- SDHC0_D2
- SDHC0_D3
- pushButton1
- SDHC0_CMD
- SDHC0_DCLK
- SDHC0_D0
- SDHC0_D1
- SD_CARD_DETECT
- pushbutton0
- Default: no shunt
- Default: no shunt
- Default: no shunt
- Default: no shunt
- CMT_IRO
- IRDA
- Intersheet References
- Default: no shunt
  (Disable IRDA)
sheet 4
- GENERAL PURPOSE
       TWRPI
- I2C0_SCL
- I2C0_SDA
- TWRPI-ADC0
- TWRPI-ADC1
- SPI2_MISO
- SPI2_MOSI
- TWRPI-ADC2
- SPI2_CS1_B
- SPI2_CLK
- TWRPI_GPIO0/IRQ
- TWRPI_GPIO1
- TWRPI-ID0
- TWRPI-ID1
- TWRPI_GPIO2
- TWRPI_GPIO3
- TWRPI_GPIO4
- Intersheet References
- Accelerometer
- TSI0_CH0
- TSI0_CH6
- TSI0_CH13
- TSI0_CH7
- TSI0_CH14
- TSI0_CH8
- I2C0_SCL
- I2C0_SDA
- TSI0_CH15
- TSI0_CH5
- TSI0_CH9
- TSI0_CH10
- TSI0_CH11
- TSI0_CH12
- IRQ1
- TOUCH TWRPI-ID0
- TOUCH TWRPI-ID1
- IRQ4
- TOUCH PAD
    TWRPI
- TSI0_CH7
- TSI0_CH9
- TSI0_CH8
- POTENTIOMETER
- TSI0_CH5
sheet 5
- NAND FLASH
- Intersheet References
- NFC_D0
- NFC_RE
- NFC_D1
- NFC_D2
- NFC_CLE
- NFC_D3
- NFC_ALE
- NFC_D4
- NFC_D5
- NFC_D6
- NFC_D7
- NFC_D8
- NFC_R/B_N
- NFC_D12
- NFC_D13
- NFC_D14
- NFC_D15
